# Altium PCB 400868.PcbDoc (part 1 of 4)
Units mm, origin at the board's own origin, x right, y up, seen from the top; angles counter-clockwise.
Board outline 117 x 63.5 mm, 4 copper layers (Top Layer, Mid-Layer 1, Mid-Layer 2, Bottom Layer), stack 1.58 mm thick; 211 components, 153 nets, 878 pads, 1351 vias.
Unrouted connection lines stored in the file: 16.
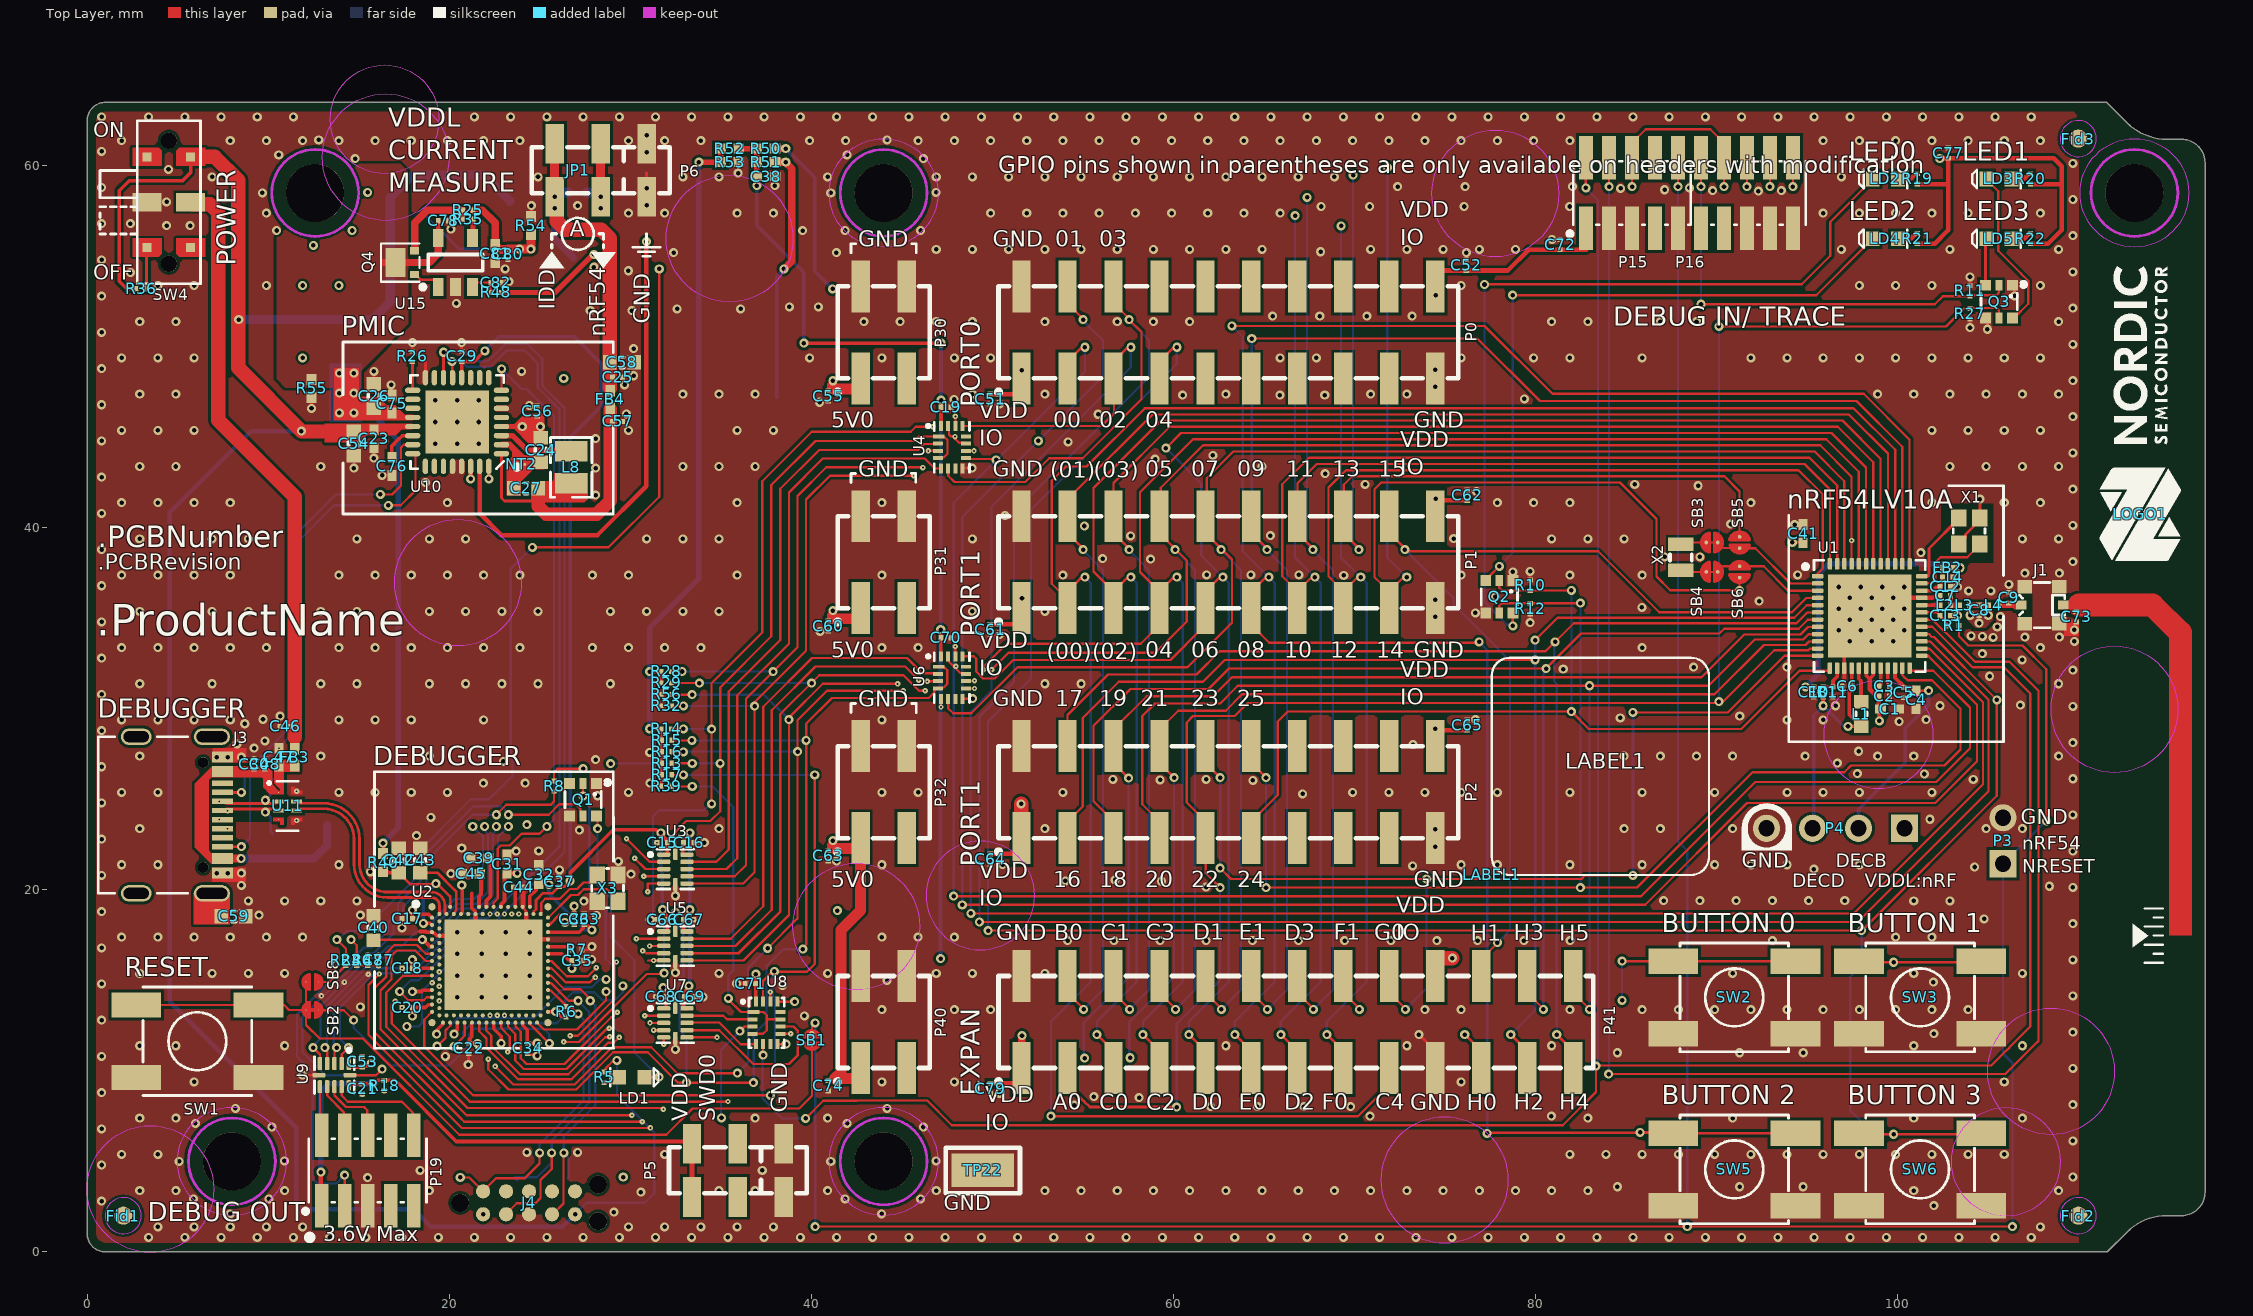
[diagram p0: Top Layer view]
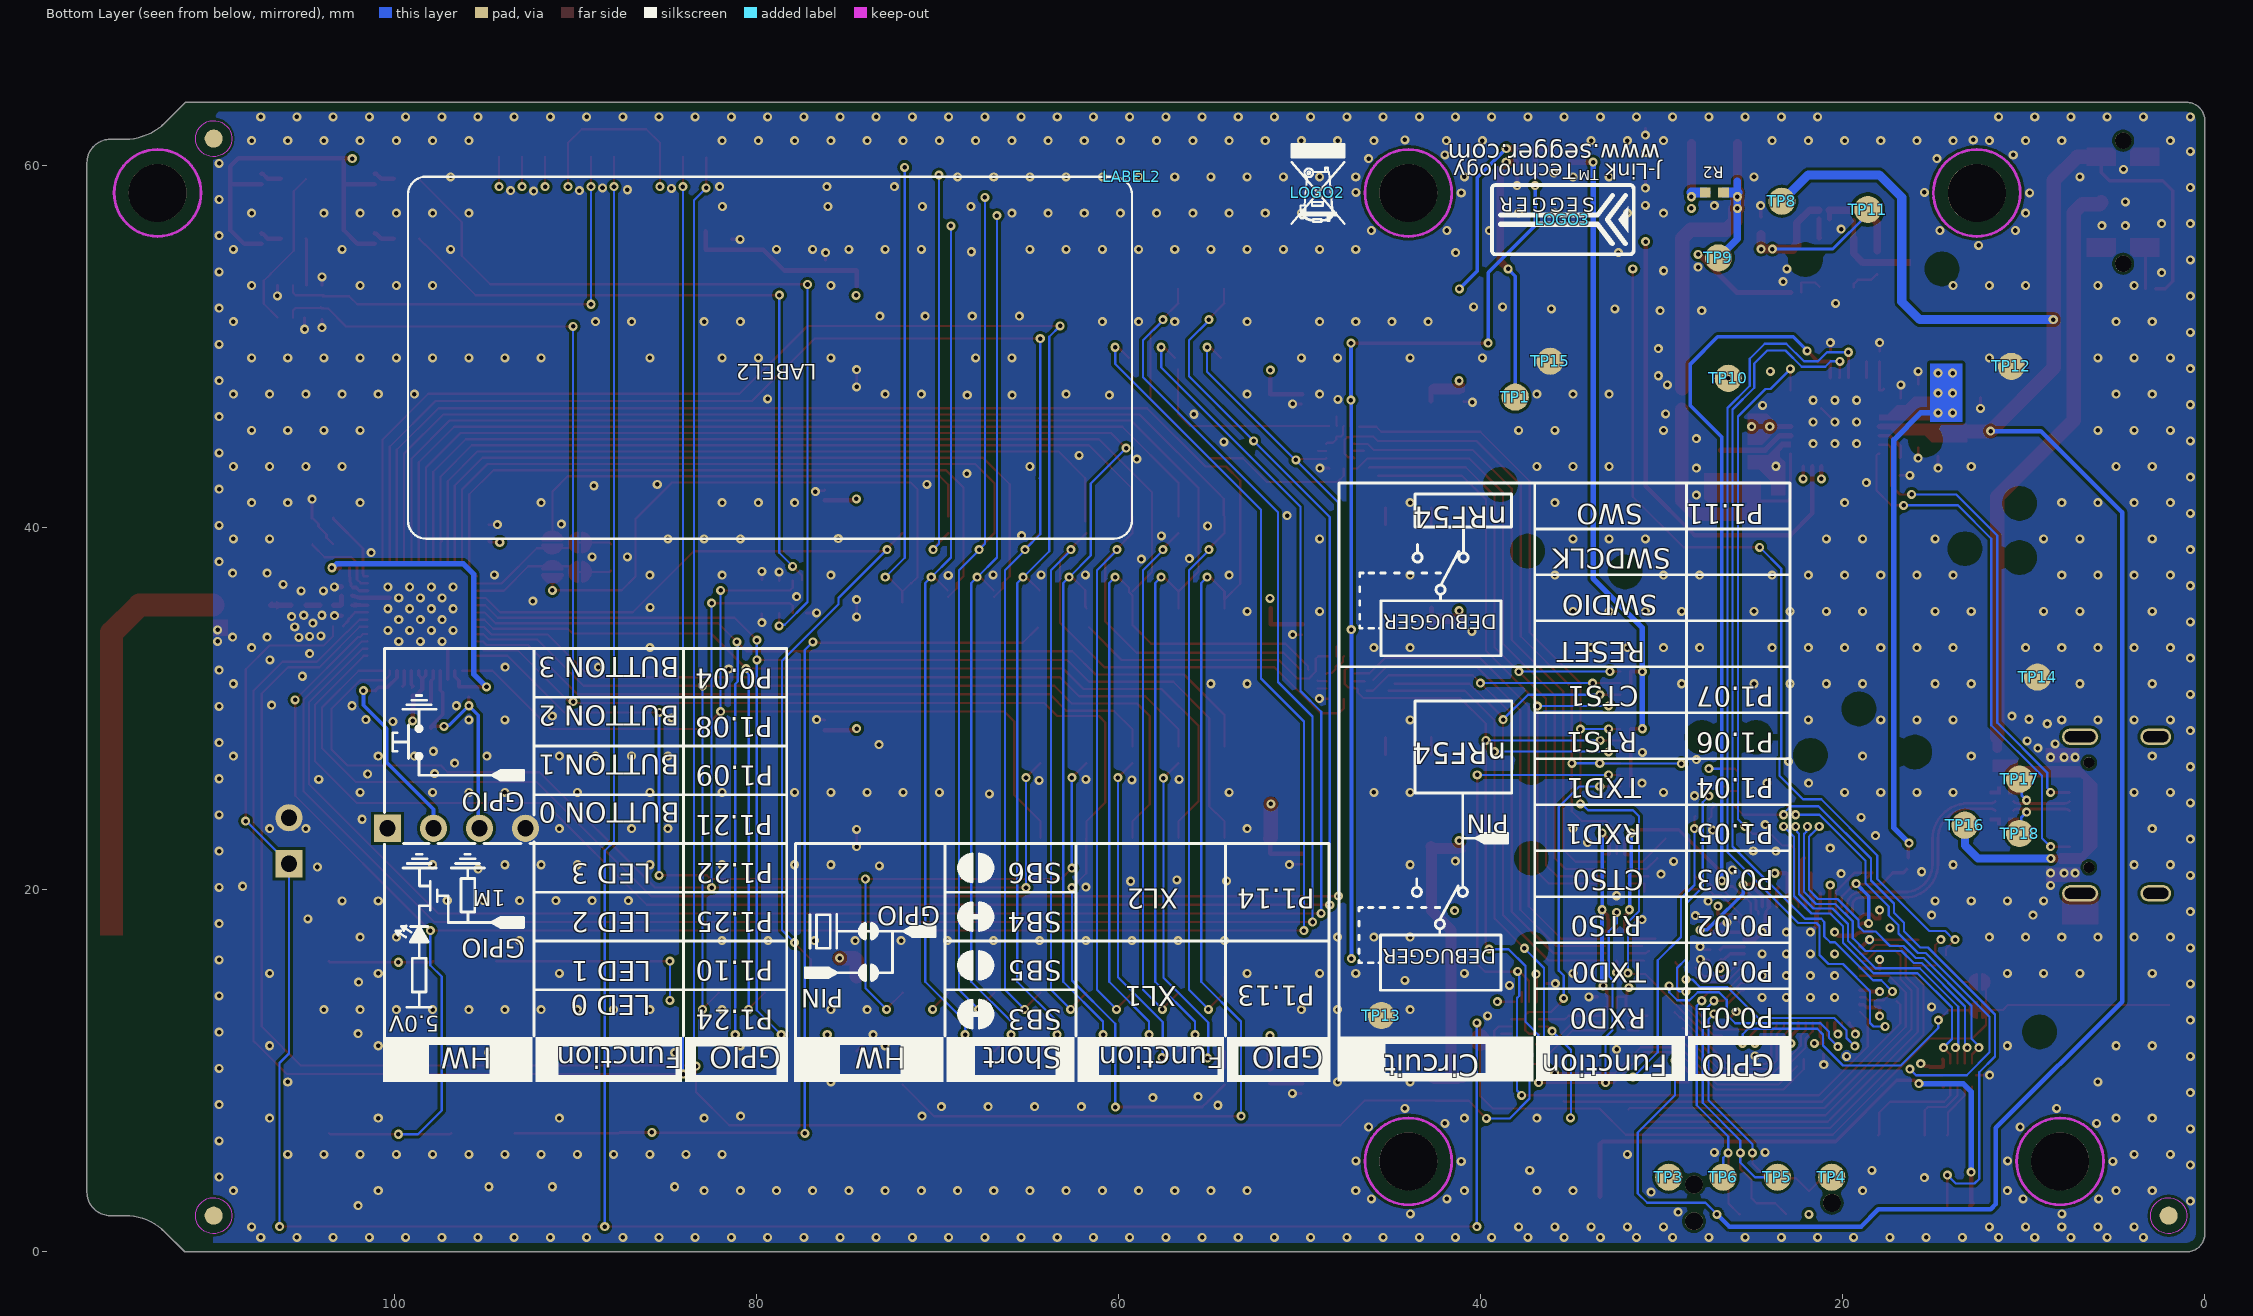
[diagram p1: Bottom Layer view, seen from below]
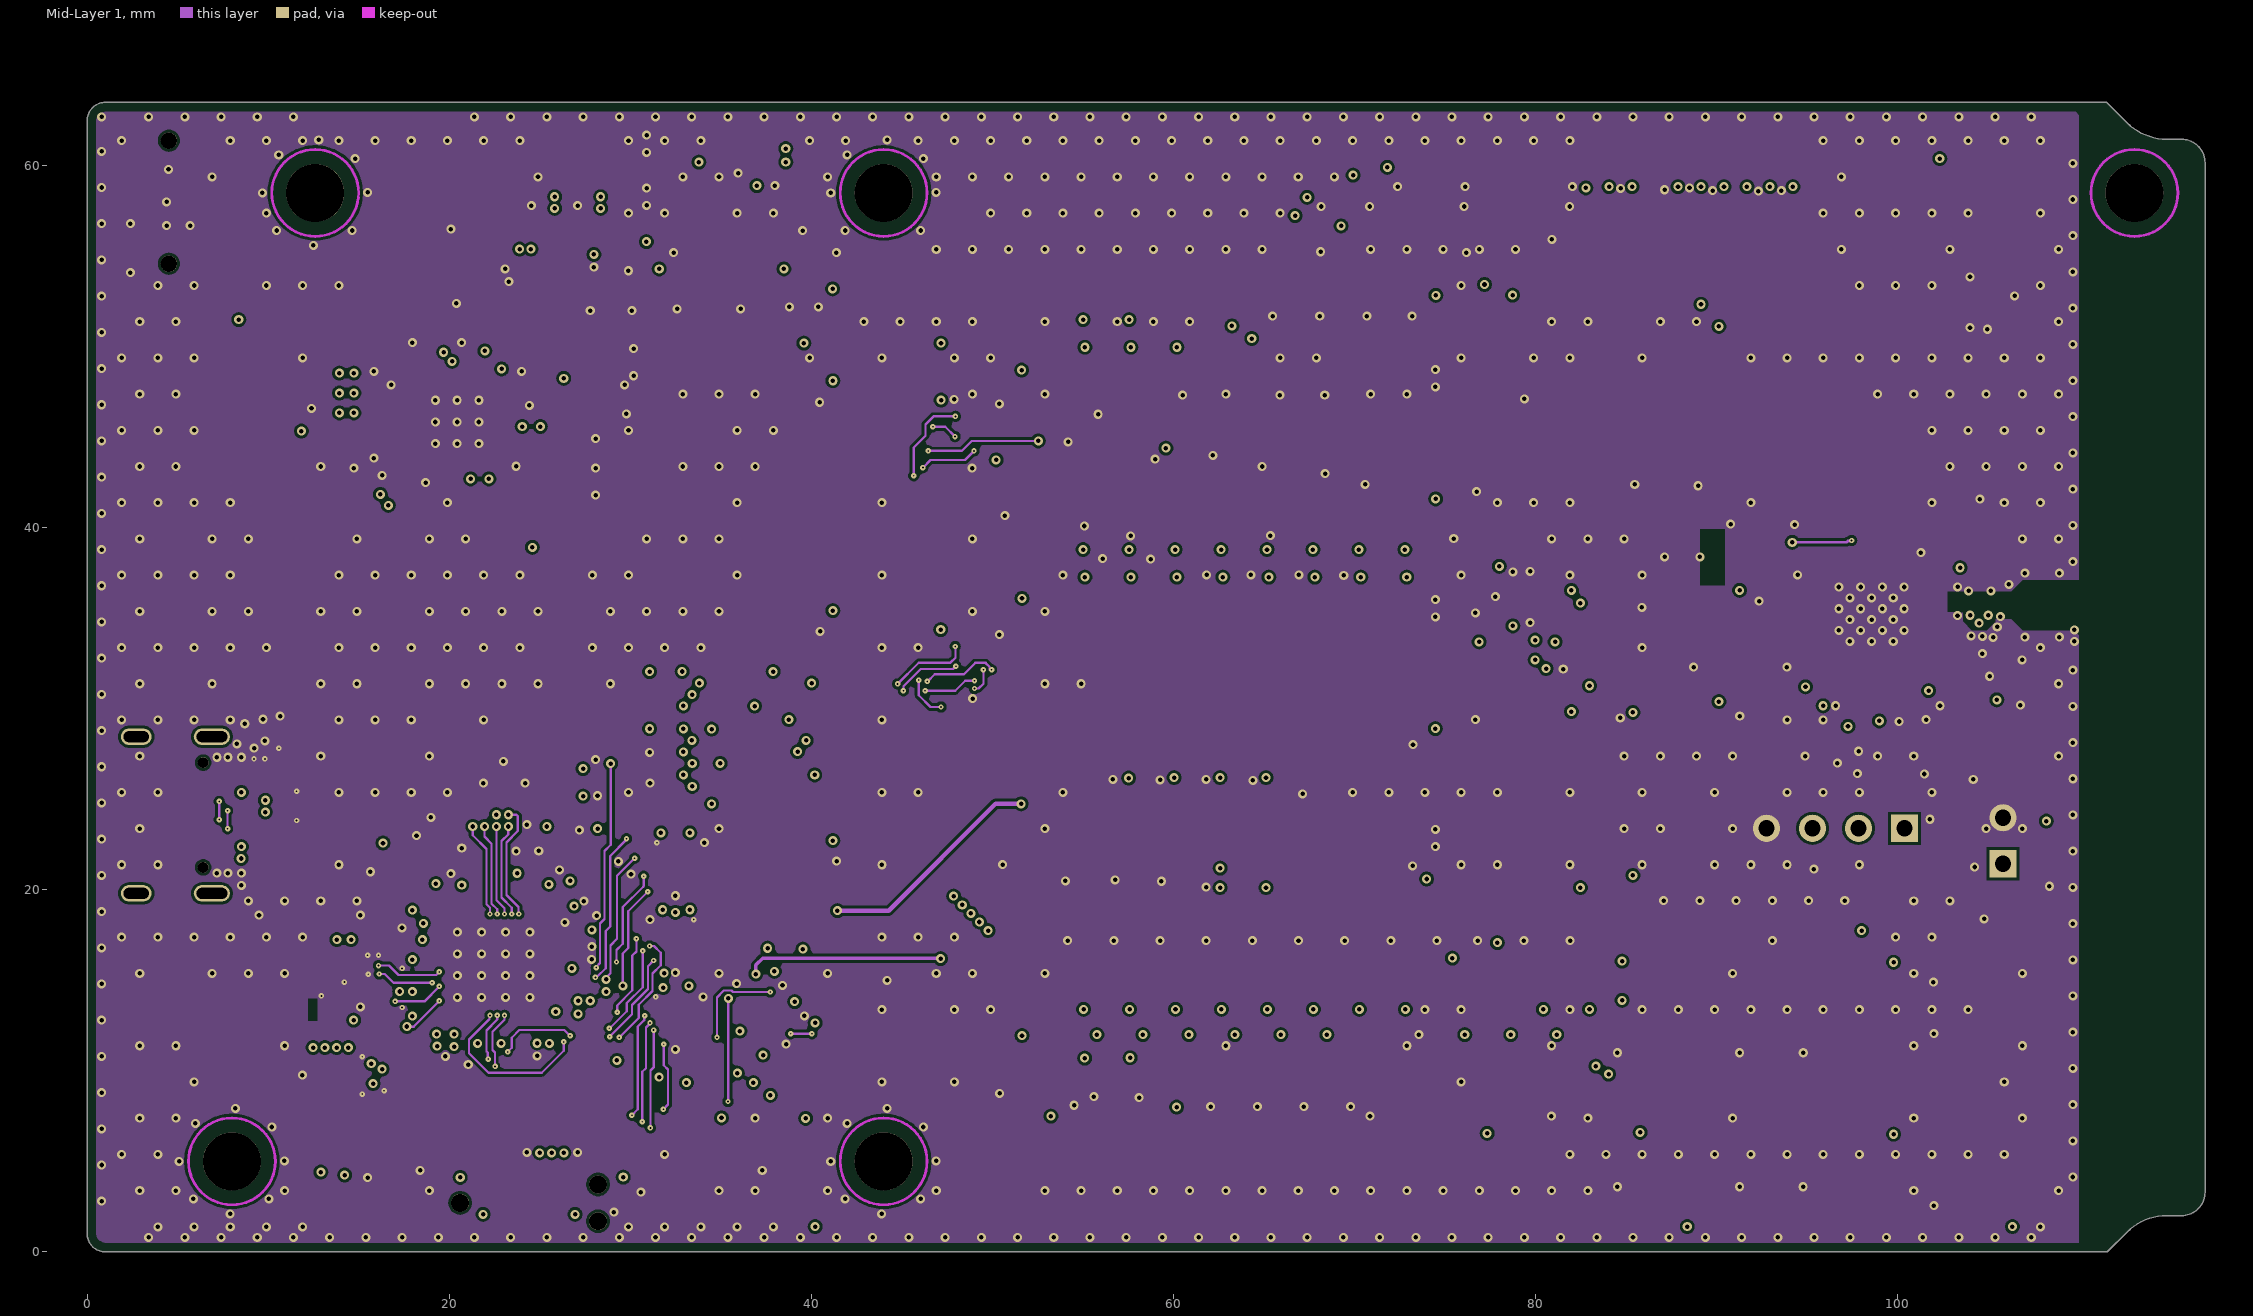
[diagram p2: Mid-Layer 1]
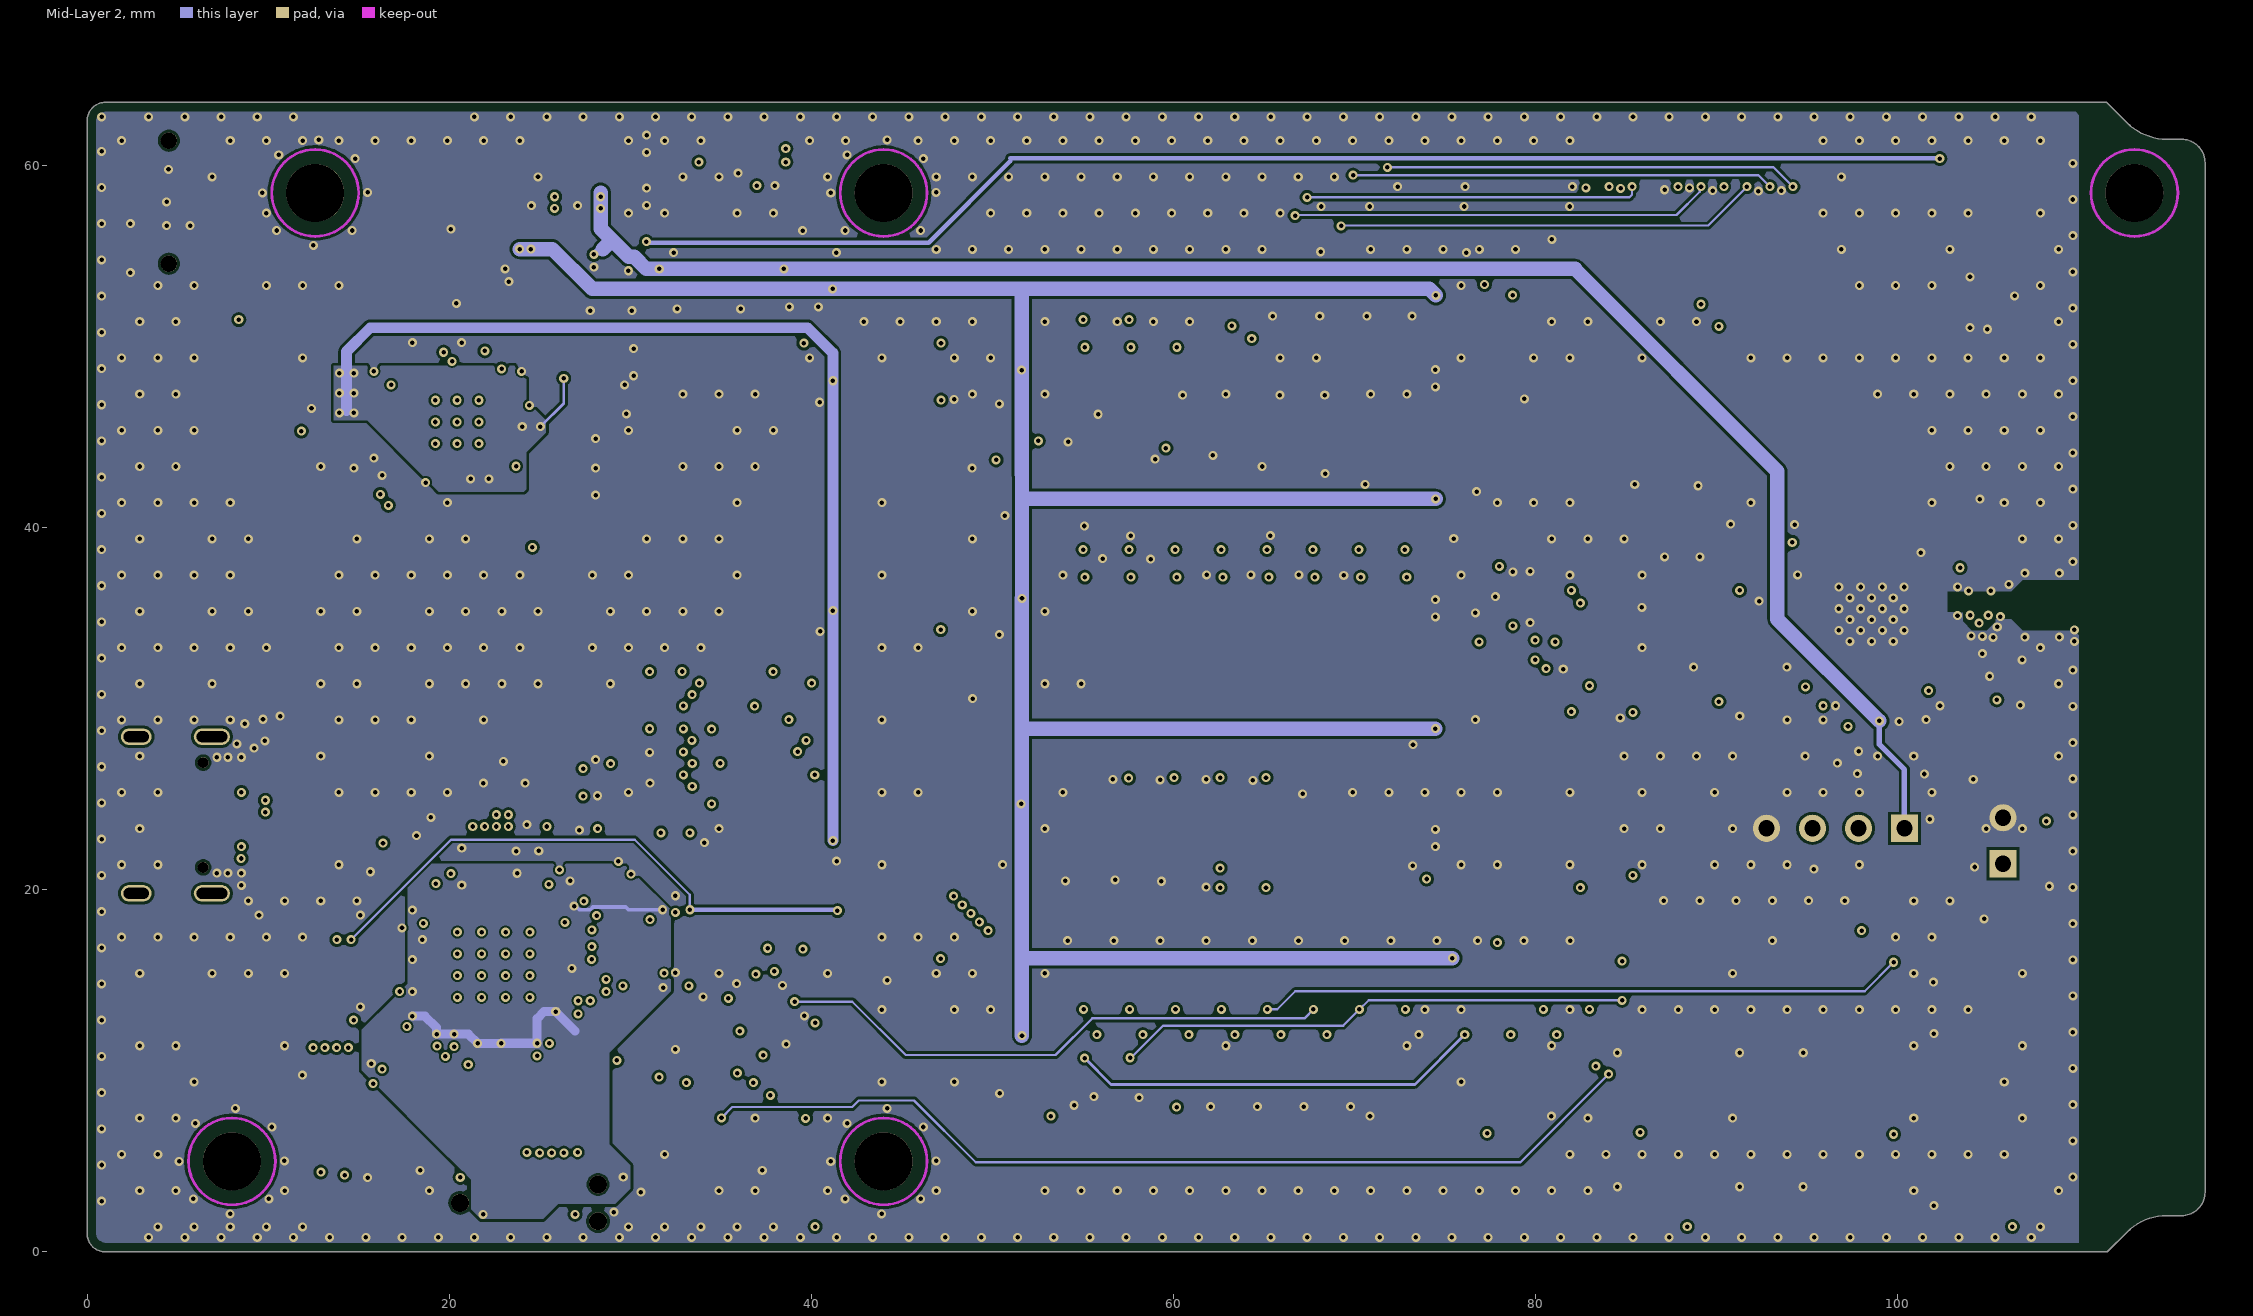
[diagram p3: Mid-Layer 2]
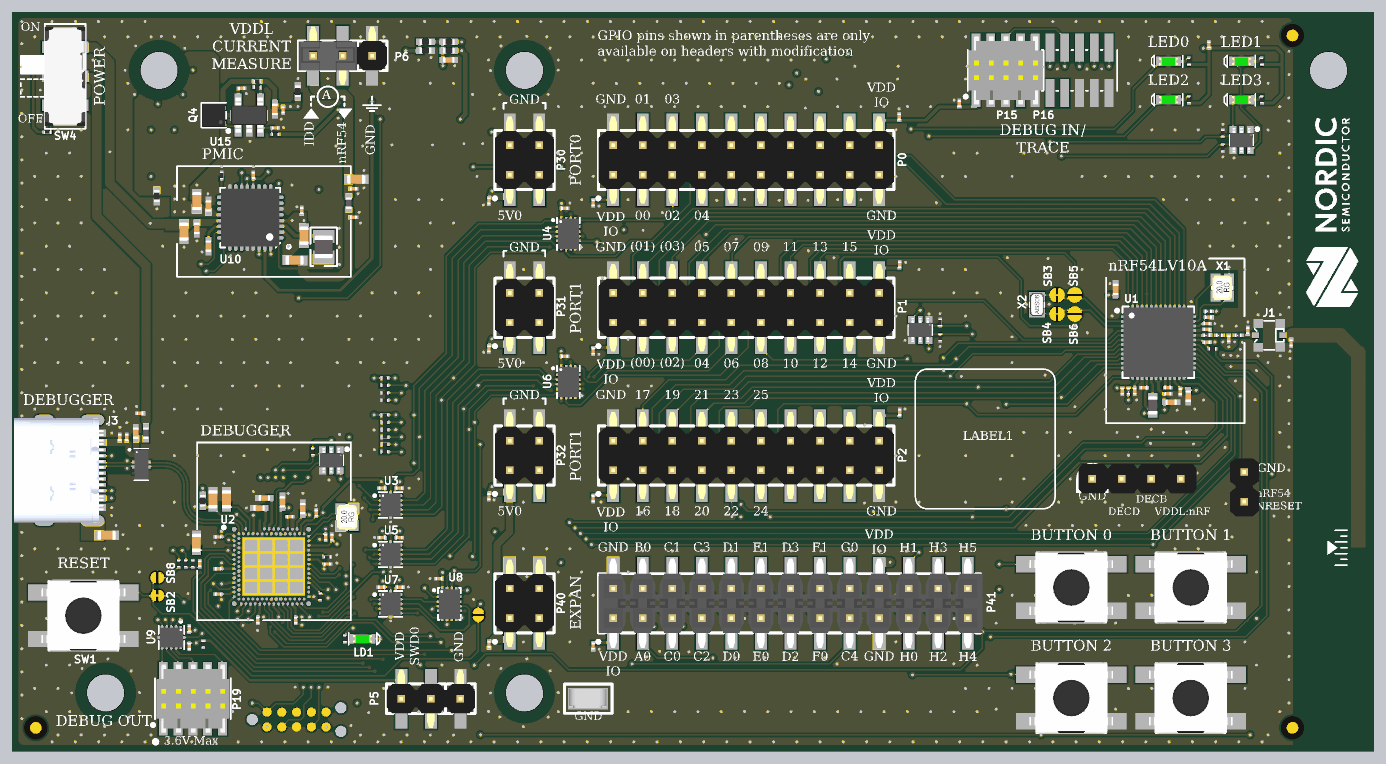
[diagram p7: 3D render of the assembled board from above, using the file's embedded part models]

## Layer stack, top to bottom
Top Solder: solder mask 0.0254, SM-003, Dk 4
Top Layer: signal copper 0.035
Dielectric 1: prepreg 0.07, PP-021, Dk 4.2
Mid-Layer 1: signal copper 0.035
Dielectric 2: core 1.3, Core-042, Dk 4.2
Mid-Layer 2: signal copper 0.035
Dielectric 3: prepreg 0.07, PP-021, Dk 4.2
Bottom Layer: signal copper 0.035
Bottom Solder: solder mask 0.0254, SM-003, Dk 4

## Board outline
1.016,0 cw(c1.016,1.016) 0,1.016 0,62.484 cw(c1.016,62.484) 1.016,63.5 111.571,63.5 112.688,62.383 ccw(c114.9,64.594) 114.9,61.467 115.709,61.467 cw(c115.709,60.171) 117.004,60.171 117.004,3.299 cw(c115.709,3.299) 115.709,2.004 114.9,2.004 ccw(c114.9,-1.123) 112.688,1.088 111.604,0.004 111.604,0

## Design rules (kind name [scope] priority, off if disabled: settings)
AssemblyTestPointUsage [All] p1 off:
AssemblyTestpoint [All] p1 off: testpointundercomponent=TRUE minsize=1.016 maxsize=2.54 preferedsize=1.524 minholesize=0 maxholesize=1.016 preferedholesize=0.813 testpointgrid=0.025 usegrid=TRUE gridtolerance=0 allowsidetop=TRUE allowsidebottom=TRUE
BoardOutlineClearance [All] p1: gap=0.508 ignorepadtopadclearanceinfootprint=FALSE except(0: Arc-SplitContinuation Track-SplitContinuation SMDPad-SplitContinuation THPad-SplitContinuation Via-SplitContinuation Fill-SplitContinuation Poly-SplitContinuation Region-SplitContinuation Text-SplitContinuation)
Clearance ANT_Clearance [InNet('PCBANT') or InNet('RF') or InNet('NetC9_2') or InNet('NetC6_2')] p1: gap=0.16 ignorepadtopadclearanceinfootprint=FALSE
Clearance Polygon_Clearance [(InNamedPolygon('Mid_Layer1-GND')) or (InNamedPolygon('Bottom_Layer-GND')) or (InNamedPolygon('Mid_Layer2-GND')) or (InNamedPolygon('Top_Layer-GND'))] p2: gap=0.15 ignorepadtopadclearanceinfootprint=FALSE
Clearance Clearance_IMCU [WithinRoom('nRF5340')] p3: gap=0.1 ignorepadtopadclearanceinfootprint=FALSE
Clearance DiffPair_Clearance [InNetClass('IMCU_USB')] p4: gap=0.125 ignorepadtopadclearanceinfootprint=FALSE
Clearance [All] p5: gap=0.125 ignorepadtopadclearanceinfootprint=FALSE
ComponentClearance [All] p1 off: gap=0.254 collisioncheckmode=3 verticalgap=0.254 showdistances=FALSE
DiffPairsRouting [InDifferentialPairClass('All Differential Pairs')] p1: maxlimit=0.15 minlimit=0.15 mostfreqgap=0.15 toplayer_minwidth=0.125 toplayer_maxwidth=0.153 toplayer_prefwidth=0.153 midlayer1_minwidth=0.125 midlayer1_maxwidth=0.153 midlayer1_prefwidth=0.125 midlayer4_minwidth=0.125 midlayer4_maxwidth=0.153 midlayer4_prefwidth=0.125 bottomlayer_minwidth=0.125 bottomlayer_maxwidth=0.153 bottomlayer_prefwidth=0.153 maxuncoupledlength=10
FabricationTestPointUsage TestPointUsage [All] p1 off: valid=2 allowmultiple=FALSE
FabricationTestpoint Testpoint [All] p1 off: side=2 testpointundercomponent=TRUE minsize=1.016 maxsize=2.54 preferedsize=1.524 minholesize=0 maxholesize=1.016 preferedholesize=0.813 testpointgrid=2.54 allowsidebottom=TRUE usegrid=TRUE gridtolerance=0
Height [All] p1 off: minheight=0 maxheight=25.4 prefheight=12.7
HoleSize [All] p1: absolutevalues=TRUE maxlimit=5 minlimit=0.1 maxpercent=80.000 minpercent=20.000
HoleToHoleClearance [IsThruVia] p1: gap=0.35 allowstackedmicrovias=FALSE
LayerPairs [All] p1 off: enforce=TRUE
MatchedLengths "Schematic Matched Net Lengths" [InNetClass('TRACE')] p1: tolerance=25.4 checknetsindiffpair=FALSE checkdiffpairvsdiffpair=TRUE checkxsignals=TRUE checkothers=TRUE usedelayunits=TRUE delaytolerance=500.000000
MatchedLengths MatchedLengths-Diffpairs [InDifferentialPairClass('All Differential Pairs')] p2: tolerance=1.27 checknetsindiffpair=TRUE checkdiffpairvsdiffpair=FALSE checkxsignals=FALSE checkothers=FALSE
MinimumAnnularRing [All] p1 off: minimumring=0.1
MinimumSolderMaskSliver [All] p1: minsoldermaskwidth=0.09
NetAntennae [All] p1 off: netantennaetolerance=0.3
PolygonConnect Direct_TP_GND [HasFootprint('TP_SMD_D1.5mm') vs InNet('GND')] p1: connectstyle=Direct reliefconductorwidth=0.254 reliefentries=4 polygonreliefangle="90 Angle" airgapwidth=0.254
PolygonConnect Direct [IsPolygon] p2: connectstyle=Direct reliefconductorwidth=0.254 reliefentries=4 polygonreliefangle="90 Angle" airgapwidth=0.254
PolygonConnect [All] p3: thpad.connectstyle=Relief thpad.reliefconductorwidth=0.254 thpad.reliefentries=4 thpad.polygonreliefangle="90 Angle" thpad.airgapwidth=0.2 smdpad.connectstyle=Relief smdpad.reliefconductorwidth=0.254 smdpad.reliefentries=4 smdpad.polygonreliefangle="90 Angle" smdpad.airgapwidth=0.2 via.connectstyle=Direct via.reliefconductorwidth=0.254 via.reliefentries=4 via.polygonreliefangle="90 Angle" via.airgapwidth=0.254
RoomDefinition nRF5340 [False vs False] p1: confinementstyle=ConfineIn formatcopy=TRUE lockcomponents=FALSE outline 17.46,20.1 27.2,20.1 27.2,10.6 17.46,10.6
RoutingVias RoutingVias_Blind [IsBlindVia or IsMicroVia] p1: holewidth=0.711 width=1.27 viastyle="Through Hole" minholewidth=0.711 minwidth=1.27 maxholewidth=0.711 maxwidth=1.27 useviatemplates=TRUE viatemplateguid#1={B6F7EE11-84B8-42C4-BDC0-4B8B407402DD} viatemplatename#1=v30h10m0
RoutingVias RoutingVias_thru [IsThruVia] p2: holewidth=0.305 width=0.61 viastyle="Through Hole" minholewidth=0.305 minwidth=0.61 maxholewidth=0.711 maxwidth=1.27 useviatemplates=TRUE viatemplateguid#1={462064FF-42C7-473E-A651-561C1576AFDF} viatemplateguid#2={72C71B86-6CEB-4856-99C3-3AF46C3BA652} viatemplatename#1=v50h25m0mx0 viatemplatename#2=v50h25m0mx0(2)
ShortCircuit ShortCircuit_P15_P16 [InComponent('P15') vs InComponent('P16')] p1: allowed=TRUE
ShortCircuit ShortCircuit_PSS [InNet('PVSS1') or InNet('PVSS2') vs InNet('GND')] p2: allowed=TRUE
ShortCircuit [All] p3: allowed=FALSE
SilkToSilkClearance [All] p1 off: silktosilkclearance=0.254
SilkToSolderMaskClearance SilkscreenOverComponentPads [IsPad] p1 off: minsilkscreentomaskgap=0.254 clearancetoexposedcopper=TRUE
SolderMaskExpansion SolderMaskExpansion_XFDFN40 [HasFootprint('XFDFN40P180X120X40-8M') or HasFootprint('XQFN40P180X260X50-16N')] p1: expansion=0.02 istentingtop=FALSE
SolderMaskExpansion SolderMaskExpansion_footprints [HasFootprint('UDFN65P200X200X60_HS-6N') or HasFootprint('SON50P300X80-HS-11N') or HasFootprint('US8') or HasFootprint('SON50P300X80_HS-9N') or HasFootprint('BGA25C40P5X5_200X200X50') or HasFootprint('QFN40P180X140X55-10N') or HasFootprint('DX07S016JA1R1500') or HasFootprint('AQFN40P700X700X85_HS-99N') or HasFootprint('Nordic_QFN50P500X500X90-33N') or HasFootprint('QFN12P40_170X200X55L50X20')] p2: expansion=0.03 istentingtop=FALSE
SolderMaskExpansion SolderMaskExpansion_VIA [IsVia] p3: expansion=0.076 istentingtop=TRUE
SolderMaskExpansion PadsInPolygon [InNamedPolygon('Top_Layer-GND')] p4: expansion=0.02 istentingtop=FALSE
SolderMaskExpansion [All] p5: expansion=0.05 istentingtop=FALSE
Width Width_IMCU [OnTopLayer and HasFootprint('BGA144C35P12X12_450X420X100-A8-M3')] p1: maxlimit=2.5 minlimit=0.1 preferedwidth=0.15
Width [All] p2: maxlimit=2.5 minlimit=0.125 preferedwidth=0.15
15 further rules are at their usual default settings.

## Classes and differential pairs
net class UART1: P1.04 P1.05 P1.06 P1.07
net class UART0: P0.00 P0.01 P0.02 P0.03
net class SWD_nRF54: nRF54_NRESET P1.11 SWDCLK SWDIO
net class LEDS: P1.10 P1.22 P1.24 P1.25
net class GPIO_P1: P1.00 P1.01 P1.02 P1.03 P1.04 P1.05 P1.06 P1.07 P1.08 P1.09 P1.10 P1.11 P1.12 P1.13 P1.14 P1.15 P1.16 P1.17 P1.18 P1.19 P1.20 P1.21 P1.22 P1.23 P1.24 P1.25
net class GPIO_P0: P0.00 P0.01 P0.02 P0.03 P0.04
net class BUTTONS: P0.04 P1.08 P1.09 P1.21
differential pair class IMCU: D DBGR DBGR'
net class TRACE: P1.10 P1.11 P1.12 P1.13 P1.14
net class IMCU_USB: D_N D_P DBGR_N DBGR_P
component class "Power supply": C23 C24 C25 C26 C27 C29 C56 C57 C58 C75 C76 C78 C80 C81 C82 FB4 JP1 L8 NT2 P6 Q4 R2 R25 R26 R35 R48 R54 R55 TP1 TP8 TP9 TP10 TP11 TP12 TP13 TP14 TP15 U10 U15
component class "Levelshifters and switches": C15 C16 C19 C21 C38 C53 C66 C67 C68 C69 C70 C71 R8 R13 R14 R15 R16 R17 R18 R28 R29 R32 R39 R50 R51 R52 R53 R56 U3 U4 U5 U6 U7 U8 U9
component class nRF54LV10A: C1 C2 C3 C4 C5 C6 C7 C8 C9 C10 C11 C12 C13 C14 C41 C73 FB1 FB2 J1 L1 L2 L3 L4 P3 P4 R1 SB3 SB4 SB5 SB6 U1 X1 X2
component class Debugger: C17 C18 C20 C22 C31 C32 C33 C34 C35 C36 C37 C39 C40 C42 C43 C44 C45 C87 J4 LD1 Q1 R5 R6 R7 R40 R46 R47 TP3 TP4 TP5 TP6 U2 X3
component class Misc: C77 LD2 LD3 LD4 LD5 Q2 Q3 R10 R11 R12 R19 R20 R21 R22 R23 R27 SB8 SW1 SW2 SW3 SW5 SW6
component class Connectors: C30 C46 C47 C48 C51 C52 C54 C55 C59 C60 C61 C62 C63 C64 C65 C72 C74 C79 FB3 J3 P0 P1 P2 P5 P15 P16 P19 P30 P31 P32 P40 P41 R36 SW4 TP16 TP17 TP18 TP22 U11
component class pca10188_sheet1_cover_sheet: Fid1 Fid2 Fid3 LABEL1 LABEL2 LOGO1 LOGO2 LOGO3 SB1 SB2
differential pair D: +D_P -D_N
differential pair DBGR: +DBGR_P -DBGR_N

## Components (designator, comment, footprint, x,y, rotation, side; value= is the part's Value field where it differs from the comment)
C1 "10µF" CAPC1005X04L#1 99.58,29.98 r180 top
C2 "100nF" CAPC0603X03L_C#1 99.28,30.705 r180 top
C3 "1.0µF" CAPC0603X03L_C#2 99.28,31.237 r0 top
C4 "10µF" CAPC1005X04L#1 101.048,30.503 r90 top
C5 "100nF" CAPC0603X03L_C#3 100.355,30.902 r270 top
C6 "4.7µF" CAPC0603X03L_C#1 97.239,31.237 r0 top
C7 "1.5pF" CAPC0603X03L_C#1 102.648,36.237 r0 top
C8 "2.0pF" CAPC0603X03L_C#1 104.527,35.444 r90 top
C9 "0.3pF" CAPC0603X03L_C#1 106.166,36.135 r270 top
C10 "2.2µF" CAPC0603X03L_C#1 95.377,30.93 r90 top
C11 "10nF" CAPC0603X03L_C#1 96.451,30.93 r90 top
C12 "1.0nF" CAPC0603X03L_C#1 102.648,36.745 r180 top
C13 "3.9pF" CAPC0603X03L_C#1 102.648,35.144 r180 top
C14 "2.2µF" CAPC0603X03L_C#2 102.786,37.282 r180 top
C15 "100nF" CAPC0603X03L_C#1 31.766,22.604 r0 top
C16 "100nF" CAPC0603X03L_C#3 33.233,22.604 r0 top
C17 "100nF" CAPC0603X03L_C#3 17.689,18.401 r180 top
C18 "100nF" CAPC0603X03L_C#3 17.689,15.659 r180 top
C19 "100nF" CAPC0603X03L_C#3 47.45,46.65 r0 top
C20 "100nF" CAPC0603X03L_C#3 17.689,13.499 r180 top
C21 "100nF" CAPC0603X03L_C#3 15.2,9 r270 top
C22 "100nF" CAPC0603X03L_C#3 21.092,11.239 r270 top
C23 "2.2µF" CAPC1005X04L#1 15.842,44.921 r90 top
C24 "10µF" CAPC1608X06L#1 25.067,44.296 r90 top
C25 "100nF" CAPC0603X03L_C#1 29.305,48.321 r180 top
C26 "10µF" CAPC1608X06L#2 15.842,47.271 r270 top
C27 "10µF" CAPC1608X06L#1 24.249,42.186 r0 top
C29 "100nF" CAPC0603X03L_C#3 20.692,49.468 r90 top
C30 "10nF" CAPC0603X03L_C#3 9.225,26.95 r90 top
C31 "1.0µF" CAPC1005X04L#2 23.201,21.424 r90 top
C32 "1.0µF" CAPC1005X04L#1 24.953,20.84 r270 top
C33 "2.2nF" CAPC0603X03L_C#3 27.459,18.376 r90 top
C34 "100nF" CAPC0603X03L_C#3 24.344,11.239 r270 top
C35 "100nF" CAPC0603X03L_C#3 27.068,16.078 r0 top
C36 "100nF" CAPC0603X03L_C#3 26.909,18.376 r270 top
C37 "100nF" CAPC0603X03L_C#3 26.096,20.459 r90 top
C38 "1.0µF" CAPC1005X04L#1 37.5,59.4 r180 top
C39 "1.0µF" CAPC1005X04L#1 21.651,21.754 r0 top
C40 "2.2µF" CAPC1608X06L#3 15.825,17.9 r90 top
C41 "100nF" CAPC1005X04L#1 94.804,39.675 r270 top
C42 "4.7µF" CAPC1608X06L#3 17.232,21.627 r90 top
C43 "4.7µF" CAPC1608X06L#3 18.4,21.627 r90 top
C44 "100nF" CAPC0603X03L_C#3 23.836,20.154 r0 top
C45 "1.0µF" CAPC1005X04L#1 21.194,20.891 r0 top
C46 "100nF" CAPC0603X03L_C#1 10.95,29.025 r0 top
C47 "1.0µF" CAPC1005X04L#1 10.6,27.325 r270 top
C48 "100nF" CAPC0603X03L_C#1 9.825,26.95 r270 top
C51 "100nF" CAPC0603X03L_C#1 49.9,47.116 r90 top
C52 "100nF" CAPC0603X03L_C#1 76.2,54.5 r270 top
C53 "100nF" CAPC0603X03L_C#1 15.2,10.5 r270 top
C54 "4.7µF" CAPC1608X06L#3 14.742,44.646 r270 top
C55 "100nF" CAPC0603X03L_C#1 40.95,47.275 r90 top
C56 "100nF" CAPC0603X03L_C#1 24.867,46.446 r270 top
C57 "100nF" CAPC0603X03L_C#1 29.305,45.874 r180 top
C58 "4.7µF" CAPC1608X06L#3 29.55,49.139 r0 top
C59 "10nF" CAPC1608X06L#3 8.1,18.552 r0 top
C60 "100nF" CAPC0603X03L_C#1 40.95,34.575 r90 top
C61 "100nF" CAPC0603X03L_C#1 49.9,34.375 r90 top
C62 "100nF" CAPC0603X03L_C#1 76.25,41.8 r270 top
C63 "100nF" CAPC0603X03L_C#1 40.95,21.875 r90 top
C64 "100nF" CAPC0603X03L_C#1 49.9,21.7 r90 top
C65 "100nF" CAPC0603X03L_C#1 76.25,29.1 r270 top
C66 "100nF" CAPC0603X03L_C#1 31.766,18.354 r0 top
C67 "100nF" CAPC0603X03L_C#3 33.233,18.354 r0 top
C68 "100nF" CAPC0603X03L_C#1 31.704,14.085 r0 top
C69 "100nF" CAPC0603X03L_C#3 33.3,14.085 r0 top
C70 "100nF" CAPC0603X03L_C#3 47.45,33.925 r0 top
C71 "100nF" CAPC0603X03L_C#3 36.645,14.825 r180 top
C72 "100nF" CAPC0603X03L_C#1 81.372,55.65 r270 top
C73 "1.8pF" CAPC0603X03L_C#1 109.88,35.08 r90 top locked
C74 "100nF" CAPC0603X03L_C#2 40.95,9.175 r90 top
C75 "1.0µF" CAPC1005X04L#1 16.842,46.846 r270 top
C76 "1.0µF" CAPC1005X04L#1 16.842,43.396 r90 top
C77 "100nF" CAPC0603X03L_C#1 102.825,60.7 r270 top
C78 "100nF" CAPC0603X03L_C#3 19.685,56.975 r0 top
C79 "100nF" CAPC0603X03L_C#2 49.9,9.025 r90 top
C80 "100nF" CAPC0603X03L_C#3 23.254,55.1 r270 top
C81 "1.0µF" CAPC1005X04L#1 22.55,55.15 r90 top
C82 "100nF" CAPC0603X03L_C#3 22.585,53.55 r0 top
C87 "10nF" CAPC0603X03L_C#3 16.1,16.1 r90 top
FB1 "120R/0.2A" INDC0603X03L_C 95.91,30.93 r90 top
FB2 "120R/0.2A" INDC0603X03L_C 102.786,37.795 r0 top
FB3 "120R/0.55A" INDC1005X04L 11.475,27.325 r90 top
FB4 "120R/0.55A" INDC1005X04L 28.905,47.096 r90 top
Fid1 "Fiducial mark" Fiducial 2.004,2 r0 top value=N.A.
Fid2 "Fiducial mark" Fiducial 110.004,2 r0 top locked value=N.A.
Fid3 "Fiducial mark" Fiducial 110.004,61.5 r0 top locked value=N.A.
J1 "MM8130-2600" COAXIAL-SWF 108.005,35.73 r90 top locked
J3 "USB-C 2.0" SD-80259-001 5.1,24.134 r270 top locked
J4 "TC2050-IDC" TC2050-IDC-NLFP 24.418,2.709 r0 top locked
JP1 "Shunt 2.54mm" Shunt_2.54mm_Vertical 27.113,59.754 r180 top
L1 "4.7µH" INDC1608X06L 98.001,29.71 r270 top
L2 "2.7nH" INDC0603X03L_C 102.648,35.73 r0 top
L3 "3.5nH" INDC0603X03L_C 103.715,35.73 r0 top
L4 "3.5nH" INDC0603X03L_C 105.34,35.73 r0 top
L8 "2.2µH" INDC2016X10N 26.749,43.336 r90 top
LABEL1 "12x12mm" LabelSilk_12x12 77.6,20.825 r0 top
LABEL2 "20x40mm" LabelSilk_20x40 59.275,59.4 r0 bottom
LD1 "L0603G" LED_0603_G 30.103,9.652 r180 top
LD2 "L0603G" LED_0603_G 99.35,59.275 r0 top
LD3 "L0603G" LED_0603_G 105.612,59.275 r0 top
LD4 "L0603G" LED_0603_G 99.35,55.975 r0 top
LD5 "L0603G" LED_0603_G 105.612,55.975 r0 top
LOGO1 "Nordic Logo" NORDIC_LOGO_LYING 113.429,40.75 r90 top
LOGO2 "WEE Symbol" WEE_3x4.5mm 49,58.5 r0 bottom
LOGO3 "Segger Logo S" SEGGER_LOGO_S 35.475,57.025 r0 bottom
NT2 "Net tie" "2 PIN STARPOINT" 23.983,43.502 r180 top net-tie
P0 "Pin Hdr 2x10" HDR_2x10-SMD 63.054,50.8 r0 top locked
P1 "Pin Hdr 2x10" HDR_2x10-SMD 63.054,38.1 r0 top locked
P2 "Pin Hdr 2x10" HDR_2x10-SMD 63.054,25.4 r0 top locked
P3 "Pin List 1x2" LIST_1x2 105.845,22.713 r90 top
P4 "Pin List 1x4" LIST_1x4 96.59,23.4 r180 top
P5 "Pin List 1x3" LIST_1x3_SMD 38.5,4.5 r180 top locked
P6 "Pin List 1x3" LIST_1x3_SMD 30.915,59.754 r180 top
P15 "Pin Header 2x5, 1.27mm" HDR_2x5-SMD-1.27mm-K#1 85.35,58.5 r0 top
P16 "Pin Header 2x10, 1.27mm" HDR_2x10-SMD-1.27mm-NC 88.525,58.5 r0 top
P19 "Pin Header 2x5, 1.27mm" HDR_2x5-SMD-1.27mm-K#2 15.504,4.5 r0 top locked
P30 "Pin Header 2x2 SMD" HDR_2x2-SMD#1 44.004,50.8 r0 top locked
P31 "Pin Header 2x2 SMD" HDR_2x2-SMD#1 44.004,38.1 r0 top locked
P32 "Pin Header 2x2 SMD" HDR_2x2-SMD#1 44.004,25.4 r0 top locked
P40 "Pin Header 2x2 SMD" HDR_2x2-SMD#2 44.004,12.7 r0 top locked
P41 "Pin Hdr 2x13" HDR_2x13-SMD 66.864,12.7 r0 top locked
Q1 "NX138AKS" TSSOP6 27.401,24.983 r180 top
Q2 "NX138AKS" TSSOP6 78.017,36.189 r180 top
Q3 "NX138AKS" TSSOP6 105.625,52.5 r180 top
Q4 "PBSS4330PA" DFN105P200X65-3N_v2 17.3,54.65 r180 top
R1 "1k" RESC0603X03L_C#1 103.126,34.579 r0 top
R2 "1R0" RESC1005X04L#1 27.102,58.52 r180 bottom
R5 "560R" RESC0603X03L_C#1 28.56,9.652 r90 top
R6 "100k" RESC0603X03L_C#1 26.46,13.271 r270 top
R7 "47R" RESC0603X03L_C#2 27.06,16.687 r0 top
R8 "100k" RESC0603X03L_C#1 25.8,25.734 r90 top
R10 "1M0" RESC0603X03L_C#2 79.719,36.828 r90 top
R11 "1M0" RESC0603X03L_C#2 104.02,53.1 r90 top
R12 "1M0" RESC0603X03L_C#2 79.725,35.525 r270 top
R13 "100k" RESC0603X03L_C#1 32.016,26.987 r0 top
R14 "100k" RESC0603X03L_C#1 32,28.888 r0 top
R15 "100k" RESC0603X03L_C#1 32.016,28.253 r0 top
R16 "100k" RESC0603X03L_C#1 32.016,27.624 r0 top
R17 "100k" RESC0603X03L_C#1 32.016,26.35 r0 top
R18 "1M0" RESC0603X03L_C#3 16.409,9.19 r90 top
R19 "220R" RESC0603X03L_C#1 101.1,59.275 r270 top
R20 "220R" RESC0603X03L_C#1 107.362,59.275 r270 top
R21 "220R" RESC0603X03L_C#1 101.1,55.975 r270 top
R22 "220R" RESC0603X03L_C#1 107.362,55.975 r270 top
R23 "100k" RESC0603X03L_C#1 14.3,16.1 r90 top
R25 "0R" RESC0603X03L_C#1 21.035,57.55 r0 top
R26 "0R" RESC0603X03L_C#2 17.973,49.468 r90 top
R27 "1M0" RESC0603X03L_C#2 104.02,51.825 r270 top
R28 "100k" RESC0603X03L_C#1 32,32.063 r0 top
R29 "100k" RESC0603X03L_C#1 32,31.428 r0 top
R32 "100k" RESC0603X03L_C#2 32,30.158 r180 top
R35 "0R" RESC0603X03L_C#1 21.035,57.05 r180 top
R36 "1k" RESC0603X03L_C#1 3,53.2 r180 top
R39 "100k" RESC0603X03L_C#1 32,25.713 r0 top
R40 "2R2" RESC1005X04L#1 16.35,21.5 r90 top
R46 "10k" RESC0603X03L_C#1 14.9,16.1 r90 top
R47 "10k" RESC0603X03L_C#3 15.5,16.1 r270 top
R48 "33k" RESC0603X03L_C#1 22.585,53 r180 top
R50 "0R" RESC1005X04L#1 37.5,60.95 r180 top
R51 "0R" RESC1005X04L#1 37.5,60.2 r180 top
R52 "0R" RESC1005X04L#1 35.5,60.95 r0 top
R53 "0R" RESC1005X04L#2 35.5,60.2 r0 top
R54 "10k" RESC1005X04L#3 24.525,56.7 r270 top
R55 "10k" RESC1005X04L#3 12.4,47.7 r90 top
R56 "100k" RESC0603X03L_C#2 32,30.793 r180 top
SB1 "Solderbridge" Solderbridge 40.045,11.7 r270 top
SB2 "Solderbridge" Solderbridge_Shorted 12.45,13.364 r0 top net-tie
SB3 "Solderbridge" Solderbridge_SHORTED_0.4 89.769,39.189 r180 top net-tie
SB4 "Solderbridge" Solderbridge_SHORTED_0.4 89.769,37.563 r180 top net-tie
SB5 "Solderbridge" Solderbridge_0.4 91.292,39.189 r90 top
SB6 "Solderbridge" Solderbridge_0.4 91.292,37.563 r270 top
SB8 "Solderbridge" Solderbridge 12.45,14.91 r0 top
SW1 "PB SW" Switch-PB-6.2x6.3mm-SMD 6.096,11.637 r180 top
SW2 "PB SW" Switch-PB-6.2x6.3mm-SMD 91,14.058 r180 top
SW3 "PB SW" Switch-PB-6.2x6.3mm-SMD 101.262,14.058 r180 top
SW4 "Switch" JS102011JAQN 4.521,57.988 r270 top
SW5 "PB SW" Switch-PB-6.2x6.3mm-SMD 91,4.558 r180 top
SW6 "PB SW" Switch-PB-6.2x6.3mm-SMD 101.262,4.558 r180 top
TP1 "Ø1.5mm,SMD" TP_SMD_D1.5mm#1 38.104,47.219 r90 bottom locked
TP3 "Ø1.5mm,SMD" TP_SMD_D1.5mm#2 29.621,4.115 r180 bottom locked
TP4 "Ø1.5mm,SMD" TP_SMD_D1.5mm#2 20.616,4.115 r180 bottom locked
TP5 "Ø1.5mm,SMD" TP_SMD_D1.5mm#2 23.616,4.115 r180 bottom locked
TP6 "Ø1.5mm,SMD" TP_SMD_D1.5mm#2 26.616,4.115 r180 bottom locked
TP8 "Ø1.5mm,SMD" TP_SMD_D1.5mm#1 23.372,58.039 r270 bottom locked
TP9 "Ø1.5mm,SMD" TP_SMD_D1.5mm#1 26.878,54.915 r270 bottom locked
TP10 "Ø1.5mm,SMD" TP_SMD_D1.5mm#1 26.334,48.26 r180 bottom locked
TP11 "Ø1.5mm,SMD" TP_SMD_D1.5mm#1 18.622,57.582 r90 bottom locked
TP12 "Ø1.5mm,SMD" TP_SMD_D1.5mm#1 10.693,48.92 r90 bottom locked
TP13 "Ø1.5mm,SMD" TP_SMD_D1.5mm#1 45.496,13.056 r90 bottom locked
TP14 "Ø1.5mm,SMD" TP_SMD_D1.5mm#1 9.25,31.75 r90 bottom locked
TP15 "Ø1.5mm,SMD" TP_SMD_D1.5mm#1 36.174,49.2 r90 bottom locked
TP16 "Ø1.5mm,SMD" TP_SMD_D1.5mm#1 13.263,23.571 r180 bottom locked
TP17 "Ø1.5mm,SMD" TP_SMD_D1.5mm#1 10.241,26.115 r180 bottom locked
TP18 "Ø1.5mm,SMD" TP_SMD_D1.5mm#1 10.241,23.113 r180 bottom locked
TP22 "TP" S1751 49.475,4.5 r0 top locked
U1 "nRF54LV10A-QFAA-AB0" QFN49P40_600x600x90L40x20T460N 98.48,35.13 r0 top
U2 "nRF5340-QKAA" AQFN40P700X700X85_HS-99N 22.26,15.864 r0 top locked
U3 "TXU0204" QFN12P40_170X200X55L50X20#1 32.5,21.15 r0 top
U4 "TMUX1511" XQFN40P180X260X50-16N#1 47.775,44.45 r0 top
U5 "TXU0204" QFN12P40_170X200X55L50X20#1 32.5,16.9 r0 top
U6 "TMUX1511" XQFN40P180X260X50-16N#2 47.775,31.725 r0 top
U7 "TXB0304" QFN12P40_170X200X55L50X20#2 32.5,12.65 r0 top
U8 "TMUX1511" XQFN40P180X260X50-16N#1 37.545,12.65 r0 top
U9 "TXB0104" QFN12P40_170X200X55L50X20#1 13.664,9.765 r270 top
U10 "nPM1300-QEAA" Nordic_QFN50P500X500X90-33N 20.442,45.846 r180 top locked
U11 "ECMF02-4CMX8" UFDFN50P120X250X55-8N 11.079,24.633 r0 top
U15 "TLV271" SOT95P280X145-5N 20.35,54.65 r90 top
X1 "32MHz" BT-XTAL_2016 103.975,39.825 r90 top
X2 "32.768kHz" XTAL_2012 88.05,38.37 r90 top
X3 "32MHz" BT-XTAL_2016 28.756,20.094 r90 top

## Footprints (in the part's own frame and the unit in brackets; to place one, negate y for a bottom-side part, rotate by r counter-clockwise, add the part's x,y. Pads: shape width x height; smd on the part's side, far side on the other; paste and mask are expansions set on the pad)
"2 PIN STARPOINT" [mil]
  round 6 smd paste-196.85 mask+0: 1(8,0)
  round 6 smd paste-196.85 mask-196.85: 2(-8,0)
  Top Layer region: -8.01,-3 7.99,-3 7.99,3 -8.01,3
AQFN40P700X700X85_HS-99N [mm] "AQFN, 98-Leads, Body 7.00x7.00mm, Pitch 0.40mm, Thermal Pad 5.4x5.0mm, IPC Medium Density"
  rect 5.4x5 smd paste-5 mask+0: 104(0.2,0)
  round 0.4 smd paste+0.012: A1(-3.2,3.2) A31(3.2,3.2) AL1(-3.2,-3.2) AL31(3.2,-3.2)
  round 0.225 smd paste+0.012: A5(-2.2,3.2) A13(-0.6,3.2) A15(-0.2,3.2) A17(0.2,3.2) A19(0.6,3.2) A21(1,3.2) A23(1.4,3.2) A27(2.2,3.2) AA1(-3.2,-1) AA31(3.2,-1) AB2(-2.8,-1.2) AC1(-3.2,-1.4) AC31(3.2,-1.4) AD2(-2.8,-1.6) AE1(-3.2,-1.8) AE31(3.2,-1.8) AF2(-2.8,-2) AG1(-3.2,-2.2) AG31(3.2,-2.2) AH2(-2.8,-2.4) AJ1(-3.2,-2.6) AJ31(3.2,-2.6) AK2(-2.8,-2.8) AK4(-2.4,-2.8) AK6(-2,-2.8) AK8(-1.6,-2.8) AK10(-1.2,-2.8) AK12(-0.8,-2.8) AK14(-0.4,-2.8) AK16(0,-2.8) AK18(0.4,-2.8) AK20(0.8,-2.8) AK22(1.2,-2.8) AK24(1.6,-2.8) AK26(2,-2.8) AK28(2.4,-2.8) AK30(2.8,-2.8) AL3(-2.6,-3.2) AL5(-2.2,-3.2) AL7(-1.8,-3.2) AL9(-1.4,-3.2) AL11(-1,-3.2) AL13(-0.6,-3.2) AL15(-0.2,-3.2) AL17(0.2,-3.2) AL19(0.6,-3.2) AL21(1,-3.2) AL23(1.4,-3.2) AL25(1.8,-3.2) AL27(2.2,-3.2) AL29(2.6,-3.2) B2(-2.8,2.8) B4(-2.4,2.8) B6(-2,2.8) B8(-1.6,2.8) B10(-1.2,2.8) B14(-0.4,2.8) B16(0,2.8) B18(0.4,2.8) B20(0.8,2.8) B22(1.2,2.8) B24(1.6,2.8) B28(2.4,2.8) B30(2.8,2.8) C1(-3.2,2.6) C31(3.2,2.6) D2(-2.8,2.4) E1(-3.2,2.2) E31(3.2,2.2) F2(-2.8,2) G31(3.2,1.8) J1(-3.2,1.4) K2(-2.8,1.2) L1(-3.2,1) L31(3.2,1) M2(-2.8,0.8) N1(-3.2,0.6) N31(3.2,0.6) P2(-2.8,0.4) R1(-3.2,0.2) R31(3.2,0.2) T2(-2.8,0) U1(-3.2,-0.2) U31(3.2,-0.2) V2(-2.8,-0.4) W1(-3.2,-0.6) W31(3.2,-0.6) Y2(-2.8,-0.8)
  round 0.225 smd paste+0.012 mask+0: A25(1.8,3.2) B12(-0.8,2.8) B26(2,2.8) G1(-3.2,1.8) H2(-2.8,1.6) J31(3.2,1.4)
  rrect15% 1.1x1 on Top Paste: ""(-1.75,-1.8) ""(-1.75,-0.6) ""(-1.75,0.6) ""(-1.75,1.8) ""(-0.45,-1.8) ""(-0.45,-0.6) ""(-0.45,0.6) ""(-0.45,1.8) ""(0.85,-1.8) ""(0.85,-0.6) ""(0.85,0.6) ""(0.85,1.8) ""(2.15,-1.8) ""(2.15,-0.6) ""(2.15,0.6) ""(2.15,1.8)
  silkscreen extent -4.22,3.23 -3.97,3.47, body extent -3.5,-3.5 3.5,3.5, height 0.85
BT-XTAL_2016 [mm] "Crystal 2.0 x 1.6 mm"
  rect 0.95x0.85 smd: 1(-0.725,-0.575) 2(0.725,-0.575) 3(0.725,0.575) 4(-0.725,0.575)
  silkscreen extent -0.12,-0.88 0.12,0.88, body extent -1.05,-0.85 1.05,0.85, height 0.56
CAPC0603X03L_C#1 [mm] "Chip Capacitor, 2-Leads, Body 0.6x0.3mm, IPC High Density"
  rect 0.27x0.3 smd mask+0: 1(-0.285,0)
  rect 0.27x0.3 smd mask+0.05: 2(0.285,0)
  body extent -0.3,-0.15 0.3,0.15, height 0.3
CAPC0603X03L_C#2 [mm] "Chip Capacitor, 2-Leads, Body 0.6x0.3mm, IPC High Density"
  rect 0.27x0.3 smd mask+0.05: 1(-0.285,0) 2(0.285,0)
  body extent -0.3,-0.15 0.3,0.15, height 0.3
CAPC0603X03L_C#3 [mm] "Chip Capacitor, 2-Leads, Body 0.6x0.3mm, IPC High Density"
  rect 0.27x0.3 smd mask+0.05: 1(-0.285,0)
  rect 0.27x0.3 smd mask+0: 2(0.285,0)
  body extent -0.3,-0.15 0.3,0.15, height 0.3
CAPC1005X04L#1 [mm] "Chip Capacitor, 2-Leads, Body 1.0x0.5mm, IPC High Density"
  rect 0.6x0.5 smd mask+0: 1(-0.5,0)
  rect 0.6x0.5 smd: 2(0.5,0)
  body extent -0.5,-0.25 0.5,0.25, height 0.5
CAPC1005X04L#2 [mm] "Chip Capacitor, 2-Leads, Body 1.0x0.5mm, IPC High Density"
  rect 0.6x0.5 smd: 1(-0.5,0)
  rect 0.6x0.5 smd mask+0: 2(0.5,0)
  body extent -0.5,-0.25 0.5,0.25, height 0.5
CAPC1608X06L#1 [mm] "Chip Capacitor, 2-Leads, Body 1.6x0.8mm, IPC High Density"
  rect 0.75x0.8 smd: 1(-0.675,0) 2(0.675,0)
  silkscreen extent -0.1,-0.3 0.1,0.3, body extent -0.8,-0.4 0.8,0.4, height 0.8
CAPC1608X06L#2 [mm] "Chip Capacitor, 2-Leads, Body 1.6x0.8mm, IPC High Density"
  rect 0.75x0.8 smd mask+0: 1(-0.675,0)
  rect 0.75x0.8 smd: 2(0.675,0)
  silkscreen extent -0.1,-0.3 0.1,0.3, body extent -0.8,-0.4 0.8,0.4, height 0.8
CAPC1608X06L#3 [mm] "Chip Capacitor, 2-Leads, Body 1.6x0.8mm, IPC High Density"
  rect 0.75x0.8 smd: 1(-0.675,0)
  rect 0.75x0.8 smd mask+0: 2(0.675,0)
  silkscreen extent -0.1,-0.3 0.1,0.3, body extent -0.8,-0.4 0.8,0.4, height 0.8
COAXIAL-SWF [mm]
  rect 0.5x0.58 smd: 1(0,1.16) 3(0,-1.16)
  rect 0.75x0.8 smd mask+0: 2(-1.025,-0.95) 2(-1.025,0.95) 2(1.025,-0.95) 2(1.025,0.95)
  Top Layer pour cut-out: 0.65,-0.55 -0.65,-0.55 -0.65,-1.35 0.65,-1.35
  Top Layer pour cut-out: -0.65,0.55 0.65,0.55 0.65,1.35 -0.65,1.35
  silkscreen extent -1.25,-1.25 1.25,1.25, body extent -1.26,-1.3 1.26,1.3, height 1.55
DFN105P200X65-3N_v2 [mm] "DFN, 3-Leads, Body 2.00x2.00mm, Pitch 1.05mm, IPC Medium Density"
  rect 0.5x0.4 smd: 1(-0.8,0.65) 2(-0.8,-0.65)
  rect 1.1x1.6 smd: 3(0.25,0)
  Top Layer region: 0.65,-0.2 1.05,-0.2 1.05,0.2 0.65,0.2
  silkscreen extent -1.2,-1.06 1.06,1.36, body extent -1,-1 1,1, height 0.65
Fiducial [mm] "Fiducial Mark"
  round 1 smd paste-2539.97 mask+0.5: 0(0,0)
  round 1 smd far side paste-2539.97 mask+0.5: 0(0,0)
  Top Layer keep-out circle w0.01: c0,0 r1
  Bottom Layer keep-out circle w0.01: c0,0 r1
HDR_2x2-SMD#1 [mil] "Board-Board Conn, Header, 4-way, 2-row"
  rect 40x113 smd: 1(-50,-100) 3(50,-100)
  rect 40x113 smd mask+0: 2(-50,100) 4(50,100)
  silkscreen extent -105,-135 100,100, body extent -100,-148 100,148, height 382
HDR_2x2-SMD#2 [mil] "Board-Board Conn, Header, 4-way, 2-row"
  rect 40x113 smd: 1(-50,-100) 2(-50,100) 3(50,-100) 4(50,100)
  silkscreen extent -105,-135 100,100, body extent -100,-148 100,148, height 382
HDR_2x5-SMD-1.27mm-K#1 [mm] "SMT MICRO HEADER, (1,27) .050\" Keying Shroud"
  rect 0.76x2.4 smd: 1(-2.54,-1.95) 2(-2.54,1.95) 4(-1.27,1.95) 6(0,1.95) 7(1.27,-1.95) 8(1.27,1.95) 10(2.54,1.95)
  rect 0.76x2.4 smd mask+0: 3(-1.27,-1.95) 5(0,-1.95) 9(2.54,-1.95)
  silkscreen extent -3.56,-2.38 3.25,1.75, body extent -3.14,-2.92 3.14,2.92, height 6.11
HDR_2x5-SMD-1.27mm-K#2 [mm] "SMT MICRO HEADER, (1,27) .050\" Keying Shroud"
  rect 0.76x2.4 smd: 1(-2.54,-1.95) 2(-2.54,1.95) 3(-1.27,-1.95) 4(-1.27,1.95) 6(0,1.95) 7(1.27,-1.95) 8(1.27,1.95) 9(2.54,-1.95) 10(2.54,1.95)
  rect 0.76x2.4 smd mask+0: 5(0,-1.95)
  silkscreen extent -3.56,-2.38 3.25,1.75, body extent -3.14,-2.92 3.14,2.92, height 6.11
HDR_2x10-SMD [mil] "Board-Board Conn, Header, 20-way, 2-row"
  rect 40x113 smd: 1(-450,-100) 3(-350,-100) 4(-350,100) 5(-250,-100) 6(-250,100) 7(-150,-100) 8(-150,100) 9(-50,-100) 10(-50,100) 11(50,-100) 12(50,100) 13(150,-100) 14(150,100) 15(250,-100) 16(250,100) 17(350,-100) 18(350,100) 20(450,100)
  rect 40x113 smd mask+0: 2(-450,100) 19(450,-100)
  silkscreen extent -505,-135 500,100, body extent -500,-148 500,148, height 382
HDR_2x10-SMD-1.27mm-NC [mm] "SMT MICRO HEADER, (1,27) .050\""
  rect 0.76x2.4 smd: 1(-5.715,-1.95) 2(-5.715,1.95) 4(-4.445,1.95) 6(-3.175,1.95) 7(-1.905,-1.95) 8(-1.905,1.95) 10(-0.635,1.95) 11(0.635,-1.95) 12(0.635,1.95) 13(1.905,-1.95) 14(1.905,1.95) 16(3.175,1.95) 18(4.445,1.95) 20(5.715,1.95)
  rect 0.76x2.4 smd mask+0: 3(-4.445,-1.95) 5(-3.175,-1.95) 9(-0.635,-1.95) 15(3.175,-1.95) 17(4.445,-1.95) 19(5.715,-1.95)
  silkscreen extent -6.73,-2.38 6.43,1.75
HDR_2x13-SMD [mil] "Board-Board Conn, Header, 26-way, 2-row"
  rect 40x113 smd: 1(-600,-100) 2(-600,100) 3(-500,-100) 4(-500,100) 5(-400,-100) 6(-400,100) 7(-300,-100) 8(-300,100) 9(-200,-100) 10(-200,100) 11(-100,-100) 12(-100,100) 13(0,-100) 14(0,100) 15(100,-100) 16(100,100) 17(200,-100) 18(200,100) 19(300,-100) 20(300,100) 21(400,-100) 22(400,100) 23(500,-100) 24(500,100) 25(600,-100) 26(600,100)
  silkscreen extent -655,-135 643,100, body extent -650,-152 650,152, height 390
INDC0603X03L_C [mm] "Chip Inductor, 2-Leads, Body 0.6x0.3mm, IPC High Density"
  rect 0.27x0.3 smd: 1(-0.285,0) 2(0.285,0)
  body extent -0.3,-0.15 0.3,0.15, height 0.3
INDC1005X04L [mm] "Chip Inductor, 2-Leads, Body 1.0x0.5mm, IPC High Density"
  rect 0.65x0.5 smd: 1(-0.475,0) 2(0.475,0)
  body extent -0.5,-0.25 0.5,0.25, height 0.5
INDC1608X06L [mm] "Chip Inductor, 2-Leads, Body 1.6x0.8mm, IPC High Density"
  rect 0.75x0.8 smd: 1(-0.675,0) 2(0.675,0)
  silkscreen extent -0.1,-0.3 0.1,0.3, body extent -0.8,-0.4 0.8,0.4, height 0.8
INDC2016X10N [mm] "Chip Inductor, 2-Leads, Body 2.00x1.60mm, IPC Medium Density"
  rect 1.13x1.82 smd: 1(-0.885,0) 2(0.885,0)
  silkscreen extent -1.65,-1.14 1.65,1.14, body extent -1,-0.8 1,0.8, height 1
JS102011JAQN [mm] "Slide Switches - DPDT, SMD, ON-ON"
  round 0.9 hole 0.9 unplated mask+0: 0(-3.4,0) 0(3.4,0)
  rect 0.5x0.5 smd: 1(-2.5,-1.2) 3(2.5,-1.2) 4(-2.5,1.2) 6(2.5,1.2)
  rect 1x1.6 smd mask+0: 2(0,-1.2)
  rect 1x1.6 smd: 5(0,1.2)
  Top Layer region: 3,-0.562 2.838,-0.4 2,-0.4 2,-2 3,-2
  Top Layer region: 3,0.562 2.838,0.4 2,0.4 2,2 3,2
  Top Layer region: -3,-0.562 -2.838,-0.4 -2,-0.4 -2,-2 -3,-2
  Top Layer region: -3,0.562 -2.838,0.4 -2,0.4 -2,2 -3,2
  silkscreen extent -4.5,-3.8 4.5,1.75, body extent -4.25,-3.75 4.25,1.75, height 3.5
LabelSilk_12x12 [mm] "PCA version label, stick-on, 12x12mm"
  silkscreen extent 0,0 12,12, body extent 0,0 12,12, height 0.05
LabelSilk_20x40 [mm] "Early Access sticker 20x40mm"
  silkscreen extent 0,0 40,20
LED_0603_G [mil] "SMD Super Bright LED, GREEN"
  rect 30x32 smd: 1(-27.5,0) 2(27.5,0)
  silkscreen extent -58,-20 48,20, body extent -32,-16 32,16, height 24
LIST_1x2 [mm] "Pin List, 2.54mm through hole"
  rect 1.5x1.5 hole 0.9: 1(-1.27,0)
  round 1.5 hole 0.9: 2(1.27,0)
  body extent -2.54,-1.27 2.44,1.23, height 8.2
LIST_1x3_SMD [mm] "Pin List, 2.54mm, SMD"
  rect 1.02x2.19 smd mask+0: 1(0,1.465) 1(0,-1.465)
  rect 1.02x2.19 smd: 2(2.54,-1.465) 2(2.54,1.465) 3(5.08,-1.465) 3(5.08,1.465)
  silkscreen extent -1.27,-1.27 6.35,1.27, body extent -1.27,-2.5 6.35,2.5, height 9.82
LIST_1x4 [mm] "Pin List, 2.54mm through hole"
  rect 1.5x1.5 hole 0.9: 1(-3.81,0)
  round 1.5 hole 0.9: 2(-1.27,0) 3(1.27,0) 4(3.81,0)
  body extent -5.18,-1.25 4.98,1.25, height 8.2
NORDIC_LOGO_LYING [mm]
  silkscreen extent -2.57,-2.24 13.7,2.24
Nordic_QFN50P500X500X90-33N [mm] "QFN32 5x5x0.85mm, 0.5mm pitch - Medium Density"
  oval 0.85x0.3 smd: 1(-2.45,1.75) 2(-2.45,1.25) 3(-2.45,0.75) 4(-2.45,0.25) 5(-2.45,-0.25) 7(-2.45,-1.25) 8(-2.45,-1.75) 17(2.45,-1.75) 18(2.45,-1.25) 19(2.45,-0.75) 20(2.45,-0.25) 21(2.45,0.25) 22(2.45,0.75) 23(2.45,1.25) 24(2.45,1.75)
  oval 0.85x0.3 smd mask+0: 6(-2.45,-0.75)
  oval 0.3x0.85 smd: 9(-1.75,-2.45) 10(-1.25,-2.45) 11(-0.75,-2.45) 12(-0.25,-2.45) 13(0.25,-2.45) 14(0.75,-2.45) 15(1.25,-2.45) 25(1.75,2.45) 26(1.25,2.45) 27(0.75,2.45) 30(-0.75,2.45) 31(-1.25,2.45) 32(-1.75,2.45)
  oval 0.3x0.85 smd mask+0: 16(1.75,-2.45) 28(0.25,2.45) 29(-0.25,2.45)
  rect 3.5x3.5 smd mask+0: 33(0,0)
  silkscreen extent -3.43,-2.57 2.57,2.62, body extent -2.5,-2.5 2.5,2.5, height 0.9
QFN12P40_170X200X55L50X20#1 [mm] "QFN, 12-Leads, Body 2,1x1,8mm (max), Pitch 0,40mm, IPC Low Density"
  rrect50% 0.72x0.25 smd: 1(-0.64,0.8) 2(-0.64,0.4) 3(-0.64,0) 4(-0.64,-0.4) 5(-0.64,-0.8) 7(0.64,-0.8) 8(0.64,-0.4) 9(0.64,0) 10(0.64,0.4) 11(0.64,0.8)
  rrect50% 0.25x0.72 smd mask+0: 6(0,-0.85)
  rrect50% 0.25x0.72 smd: 12(0,0.85)
  silkscreen extent -1.47,-1.1 1.01,1.1, body extent -0.85,-1 0.85,1, height 0.55
QFN12P40_170X200X55L50X20#2 [mm] "QFN, 12-Leads, Body 2,1x1,8mm (max), Pitch 0,40mm, IPC Low Density"
  rrect50% 0.72x0.25 smd: 1(-0.64,0.8) 2(-0.64,0.4) 3(-0.64,0) 4(-0.64,-0.4) 5(-0.64,-0.8) 7(0.64,-0.8) 8(0.64,-0.4) 9(0.64,0) 10(0.64,0.4) 11(0.64,0.8)
  rrect50% 0.25x0.72 smd: 6(0,-0.85) 12(0,0.85)
  silkscreen extent -1.47,-1.1 1.01,1.1, body extent -0.85,-1 0.85,1, height 0.55
QFN49P40_600x600x90L40x20T460N [mm] "QFN, 48-Leads, Body 6.00x6.00mm, Pitch 0.40mm, Thermal Pad 4.60x4.60mm, IPC Nominal Density"
  rrect50% 0.64x0.25 smd mask+0.03: 1(-2.88,2.2) 2(-2.88,1.8) 3(-2.88,1.4) 4(-2.88,1) 5(-2.88,0.6) 6(-2.88,0.2) 7(-2.88,-0.2) 8(-2.88,-0.6) 9(-2.88,-1) 10(-2.88,-1.4) 11(-2.88,-1.8) 12(-2.88,-2.2) 25(2.88,-2.2) 26(2.88,-1.8) 27(2.88,-1.4) 28(2.88,-1) 29(2.88,-0.6) 30(2.88,-0.2) 31(2.88,0.2) 32(2.88,0.6) 33(2.88,1) 34(2.88,1.4) 35(2.88,1.8) 36(2.88,2.2)
  rrect50% 0.25x0.64 smd mask+0.03: 13(-2.2,-2.88) 14(-1.8,-2.88) 15(-1.4,-2.88) 16(-1,-2.88) 17(-0.6,-2.88) 18(-0.2,-2.88) 19(0.2,-2.88) 20(0.6,-2.88) 21(1,-2.88) 22(1.4,-2.88) 23(1.8,-2.88) 24(2.2,-2.88) 37(2.2,2.88) 38(1.8,2.88) 39(1.4,2.88) 40(1,2.88) 41(0.6,2.88) 42(0.2,2.88) 43(-0.2,2.88) 44(-0.6,2.88) 45(-1,2.88) 46(-1.4,2.88) 47(-1.8,2.88) 48(-2.2,2.88)
  rect 4.6x4.6 smd mask+0.04: 49(0,0)
  silkscreen extent -3.67,-3.08 3.08,3.08, body extent -3,-3 3,3, height 0.9
RESC0603X03L_C#1 [mm] "Chip Resistor, 2-Leads, Body 0.6x0.3mm, IPC High Density"
  rect 0.27x0.3 smd: 1(-0.285,0) 2(0.285,0)
  body extent -0.3,-0.15 0.3,0.15, height 0.23
RESC0603X03L_C#2 [mm] "Chip Resistor, 2-Leads, Body 0.6x0.3mm, IPC High Density"
  rect 0.27x0.3 smd: 1(-0.285,0)
  rect 0.27x0.3 smd mask+0: 2(0.285,0)
  body extent -0.3,-0.15 0.3,0.15, height 0.23
RESC0603X03L_C#3 [mm] "Chip Resistor, 2-Leads, Body 0.6x0.3mm, IPC High Density"
  rect 0.27x0.3 smd mask+0: 1(-0.285,0)
  rect 0.27x0.3 smd: 2(0.285,0)
  body extent -0.3,-0.15 0.3,0.15, height 0.23
RESC1005X04L#1 [mm] "Chip Resistor, 2-Leads, Body 1.0x0.5mm, IPC High Density"
  rect 0.6x0.55 smd mask+0.05: 1(-0.5,0) 2(0.5,0)
  body extent -0.5,-0.25 0.5,0.25, height 0.3
RESC1005X04L#2 [mm] "Chip Resistor, 2-Leads, Body 1.0x0.5mm, IPC High Density"
  rect 0.6x0.55 smd mask+0.05: 1(-0.5,0)
  rect 0.6x0.55 smd mask+0: 2(0.5,0)
  body extent -0.5,-0.25 0.5,0.25, height 0.3
RESC1005X04L#3 [mm] "Chip Resistor, 2-Leads, Body 1.0x0.5mm, IPC High Density"
  rect 0.6x0.55 smd mask+0: 1(-0.5,0)
  rect 0.6x0.55 smd mask+0.05: 2(0.5,0)
  body extent -0.5,-0.25 0.5,0.25, height 0.3
S1751 [mm]
  rect 3.45x1.85 smd mask+0: 1(0,0)
  silkscreen extent -2.04,-1.25 2.06,1.25, body extent -1.67,-0.8 1.58,0.85, height 2.05
SD-80259-001 [mm] "USB TYPE C RECEPTACLE, 16 PIN"
  round 0.6 hole 0.6 unplated: 0(-2.89,1.315) 0(2.89,1.315)
  rect 0.6x1.14 smd mask+0: A1(-3.2,2.385) A12(3.2,2.385)
  rect 0.6x1.14 smd: A4(-2.4,2.385) A9(2.4,2.385)
  rect 0.3x1.14 smd: A5(-1.25,2.385) A6(-0.25,2.385) A7(0.25,2.385) A8(1.25,2.385) B5(1.75,2.385) B6(0.75,2.385) B7(-0.75,2.385) B8(-1.75,2.385)
  oval 0.9x2 hole 0.6 slot 1.7 at 90 deg: SHLD(-4.325,1.795) SHLD(4.325,1.795)
  oval 0.9x1.7 hole 0.6 slot 1.4 at 90 deg: SHLD(-4.325,-2.385) SHLD(4.325,-2.385)
  oval 0.9x2 on Top Paste: ""(-4.32,1.795) ""(4.32,1.795)
  oval 0.9x1.7 on Top Paste: ""(-4.32,-2.385) ""(4.32,-2.385)
  silkscreen extent -4.33,-4.48 4.33,0.47, body extent -4.48,-4.98 4.48,2.74, height 3.26
SEGGER_LOGO_S [mm] "Logo 7.82 mm x 3.84 mm, print overlay"
  silkscreen extent -3.91,-1.92 3.91,1.92
Shunt_2.54mm_Vertical [mm]
  body extent -2.51,-1.24 2.51,1.24, height 9
Solderbridge [mil]
  round 1 smd paste-99999: 1(-13.78,0) 2(13.78,0)
  Top Layer region: 7.49,-19.36 15.76,-15.74 21.55,-8.8 23.62,0 23.62,0 21.55,8.79 15.76,15.74 7.49,19.36 7.49,19.36 6.18,19.31 5.02,18.71 4.22,17.68 3.94,16.4 3.94,16.4 3.94,-16.4 4.22,-17.68 5.02,-18.71 6.18,-19.31 7.49,-19.36
  Top Layer region: -7.49,19.36 -15.76,15.74 -21.55,8.8 -23.62,0 -23.62,0 -21.55,-8.79 -15.76,-15.74 -7.49,-19.36 -7.49,-19.36 -6.18,-19.31 -5.02,-18.71 -4.22,-17.68 -3.94,-16.4 -3.94,-16.4 -3.94,16.4 -4.22,17.68 -5.02,18.71 -6.18,19.31 -7.49,19.36
Solderbridge_0.4 [mm]
  round 0.2 smd paste-10: 1(-0.312,0) 2(0.312,0)
  Top Layer region: -0.077,-0.553 -0.129,-0.605 -0.205,-0.554 -0.409,-0.351 -0.462,-0.292 -0.521,-0.193 -0.549,-0.099 -0.544,0.122 -0.518,0.193 -0.434,0.33 -0.351,0.411 -0.259,0.469 -0.159,0.556 -0.08,0.565
  Top Layer region: 0.077,0.553 0.203,0.512 0.335,0.424 0.409,0.351 0.462,0.292 0.521,0.193 0.549,0.099 0.544,-0.122 0.518,-0.193 0.434,-0.33 0.351,-0.411 0.152,-0.536 0.077,-0.559
  Top Layer lines w0.125: -0.156,0.557 ccw(c-0.035,0) -0.303,0.503 ccw(c-0.035,0) -0.312,-0.498 ccw(c-0.035,0) -0.153,-0.558
  Top Layer lines w0.152: 0.153,0.557 cw(c0.03,0) 0.153,-0.557
Solderbridge_Shorted [mil]
  round 1 smd paste-99999: 1(-13.78,0) 2(13.78,0)
  Top Layer region: -4.92,3.94 -4.92,-3.94 4.92,-3.94 4.92,3.94
  Top Layer region: -7.49,19.36 -15.76,15.74 -21.55,8.8 -23.62,0 -23.62,0 -21.55,-8.79 -15.76,-15.74 -7.49,-19.36 -7.49,-19.36 -6.18,-19.31 -5.02,-18.71 -4.22,-17.68 -3.94,-16.4 -3.94,-16.4 -3.94,16.4 -4.22,17.68 -5.02,18.71 -6.18,19.31 -7.49,19.36
  Top Layer region: 7.49,-19.36 15.76,-15.74 21.55,-8.8 23.62,0 23.62,0 21.55,8.79 15.76,15.74 7.49,19.36 7.49,19.36 6.18,19.31 5.02,18.71 4.22,17.68 3.94,16.4 3.94,16.4 3.94,-16.4 4.22,-17.68 5.02,-18.71 6.18,-19.31 7.49,-19.36
Solderbridge_SHORTED_0.4 [mm]
  round 0.2 smd paste-10: 1(-0.312,0) 2(0.312,0)
  Top Layer region: 0.077,0.553 0.203,0.512 0.335,0.424 0.409,0.351 0.462,0.292 0.521,0.193 0.549,0.099 0.544,-0.122 0.518,-0.193 0.434,-0.33 0.351,-0.411 0.152,-0.536 0.077,-0.559
  Top Layer region: -0.077,-0.553 -0.129,-0.605 -0.205,-0.554 -0.409,-0.351 -0.462,-0.292 -0.521,-0.193 -0.549,-0.099 -0.544,0.122 -0.518,0.193 -0.434,0.33 -0.351,0.411 -0.259,0.469 -0.159,0.556 -0.08,0.565
  Top Layer lines w0.125: 0.363,0 -0.312,0 ; 0.153,0.557 cw(c0.03,0) 0.153,-0.557 ; -0.153,-0.558 cw(c-0.035,0) -0.156,0.557
SOT95P280X145-5N [mm] "SOT23, 5-Leads, Body 2,90x2,80mm, Pitch 0,95mm, IPC Medium Density"
  rect 1x0.6 smd: 1(-1.35,0.95) 3(-1.35,-0.95) 4(1.35,-0.95) 5(1.35,0.95)
  rect 1x0.6 smd mask+0: 2(-1.35,0)
  silkscreen extent -1.47,-1.5 0.45,1.92, body extent -1.5,-1.55 1.5,1.55, height 1.45
Switch-PB-6.2x6.3mm-SMD [mm] "6.2×6.5mm TACT Switch, without ground connector"
  rect 2.75x1.4 smd mask+0: 1(-3.375,2) 1(3.375,2)
  rect 2.75x1.4 smd: 2(-3.375,-2) 2(3.375,-2)
  silkscreen extent -3,-3 3,3, body extent -3.6,-3.1 3.6,3.1, height 2.5
TC2050-IDC-NLFP [mil]
  round 39 hole 39 unplated mask+0.79: 0(-150,0) 0(150,-40) 0(150,40)
  round 31 smd paste-196.85: 1(-100,-25) 2(-50,-25) 4(50,-25) 5(100,-25) 6(100,25) 7(50,25) 8(0,25) 9(-50,25) 10(-100,25)
  round 31 smd paste-196.85 mask+0: 3(0,-25)
  Top Layer pour cut-out: -100,25 -100,-25 100,-25 100,25
TP_SMD_D1.5mm#1 [mm] "Test point - pad 1.5mm"
  round 1.5 smd paste-5: 1(0,0)
  body extent -0.75,-0.75 0.75,0.75, height 0.05
TP_SMD_D1.5mm#2 [mm] "Test point - pad 1.5mm"
  round 1.5 smd paste-5: 1(0,0.01)
  body extent -0.75,-0.75 0.75,0.75, height 0.05
TSSOP6 [mm] "TSSOP6 (SOT-363)"
  rect 0.6x0.6 smd mask+0: 1(-0.75,-0.9) 4(0.75,0.9)
  rect 0.4x0.6 smd: 2(0,-0.9) 5(0,0.9)
  rect 0.6x0.6 smd: 3(0.75,-0.9) 6(-0.75,0.9)
  silkscreen extent -1.47,-1.07 1,0.45, body extent -1,-1.05 1,1.05, height 0.93
UFDFN50P120X250X55-8N [mm]
  round 0.025 smd: 1(-0.5,0.75) 4(-0.5,-0.75)
  rect 0.6x0.2 smd: 2(-0.5,0.25) 3(-0.5,-0.25) 6(0.5,-0.25) 7(0.5,0.25)
  round 0.025 smd mask+0: 5(0.5,-0.75) 8(0.5,0.75)
  Top Layer region: -0.2,0.65 -0.8,0.65 -0.8,0.85 -0.4,0.85 -0.4,1.05 -0.2,1.05
  Top Layer region: -0.2,-1.05 -0.4,-1.05 -0.4,-0.85 -0.8,-0.85 -0.8,-0.65 -0.2,-0.65
  Top Layer region: 0.4,0.85 0.8,0.85 0.8,0.65 0.2,0.65 0.2,1.05 0.4,1.05
  Top Layer region: 0.8,-0.85 0.4,-0.85 0.4,-1.05 0.2,-1.05 0.2,-0.65 0.8,-0.65
  silkscreen extent -1.08,-1.37 0.6,1.37, body extent -0.6,-1.25 0.6,1.25, height 0.6
WEE_3x4.5mm [mm]
  silkscreen extent -1.47,-2.7 1.47,1.71
XQFN40P180X260X50-16N#1 [mm] "QFN, 16-Leads, Body 1.80x2.60mm, Pitch 0.40mm, IPC Medium Density"
  rect 0.65x0.22 smd paste-0.02: 1(-0.725,0.6)
  rect 0.55x0.22 smd paste-0.02: 2(-0.775,0.2) 3(-0.775,-0.2) 4(-0.775,-0.6) 9(0.775,-0.6) 10(0.775,-0.2) 11(0.775,0.2) 12(0.775,0.6)
  rect 0.22x0.55 smd paste-0.02: 5(-0.6,-1.175) 6(-0.2,-1.175) 7(0.2,-1.175) 13(0.6,1.175) 14(0.2,1.175) 15(-0.2,1.175) 16(-0.6,1.175)
  rect 0.22x0.55 smd paste-0.02 mask+0: 8(0.6,-1.175)
  silkscreen extent -1.36,-1.37 0.97,1.37, body extent -0.9,-1.3 0.9,1.3, height 0.55
XQFN40P180X260X50-16N#2 [mm] "QFN, 16-Leads, Body 1.80x2.60mm, Pitch 0.40mm, IPC Medium Density"
  rect 0.65x0.22 smd paste-0.02: 1(-0.725,0.6)
  rect 0.55x0.22 smd paste-0.02: 2(-0.775,0.2) 3(-0.775,-0.2) 4(-0.775,-0.6) 9(0.775,-0.6) 10(0.775,-0.2) 11(0.775,0.2) 12(0.775,0.6)
  rect 0.22x0.55 smd paste-0.02: 5(-0.6,-1.175) 6(-0.2,-1.175) 7(0.2,-1.175) 13(0.6,1.175) 14(0.2,1.175) 15(-0.2,1.175)
  rect 0.22x0.55 smd paste-0.02 mask+0: 8(0.6,-1.175)
  rect 0.22x0.55 smd paste-0.02 mask+0.05: 16(-0.6,1.175)
  silkscreen extent -1.36,-1.37 0.97,1.37, body extent -0.9,-1.3 0.9,1.3, height 0.55
XTAL_2012 [mm] "XTAL SMD 2.0 x 1.2 mm"
  rect 0.75x1.4 smd: 1(-0.725,0) 2(0.725,0)
  silkscreen extent -0.17,-0.6 0.17,0.6, body extent -1,-0.61 1,0.61, height 0.6

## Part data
C1 C4: library part C0402-10µF-6.3V-X6S, "Capacitor, X6S, ±20%, 6.3V", Manufacturer=N.A., Part number NEMS=100200478
C2: library part C0201-100n-10V-X7R, "Capacitor, X7R, ±10%, 100nF, 10V", Manufacturer=N.A., Part number NEMS=100200469
C3: library part C0201-1µ0-6.3V, "Capacitor, Ceramic, X5R, ±20%, 6.3V", Manufacturer=Murata, Manufacturer Part Number=GRM033R60J105MEA2D, Part number IPS=N.A., Part number NEMS=100200387, Supplier Part Number 1=490-7229-1-ND
C5: library part C0201-100n-10V-X7R, "Capacitor, X7R, ±10%", Manufacturer=N.A., Part number NEMS=100200469
C6: library part C0201-4.7µ-6V3-X5R-GRM035R60J475ME15J, "Capacitor, Ceramic, X5R, ±20%, 6.3V", Manufacturer=Murata, Manufacturer Part Number=GRM035R60J475ME15J, Part number IPS=N.A., Part number NEMS=100200685, Supplier Part Number 1=490-GRM035R60J475ME15JDKR-ND
C7: library part C0201-1.5p-25V-NP0-GJM0335C1E1R5WB01, "Capacitor, NP0, ±0.05pF, 25V, High Q", Manufacturer=Murata, Manufacturer Part Number=GJM0335C1E1R5WB01, Part number IPS=N.A., Part number NEMS=100200477, Supplier Part Number 1=490-11176-2-ND
C8: library part C0201-2.0p-HQ-Murata, "Capacitor, NP0, ±0.05pF, 25V", Manufacturer=Murata, Manufacturer Part Number=GJM0335C1E2R0WB01, Part number IPS=00000001775, Part number NEMS=100200419, Part number Norautron=N.A.
C9: library part C0201-0.3p-50V-GRM0335C1HR30BA01, "Capacitor, C0G, ±0.1pF, 50V", Manufacturer=Murata, Manufacturer Part Number=GRM0335C1HR30BA01, Part number IPS=N.A., Part number NEMS=100200650, Supplier Part Number 1=490-6135-2-ND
